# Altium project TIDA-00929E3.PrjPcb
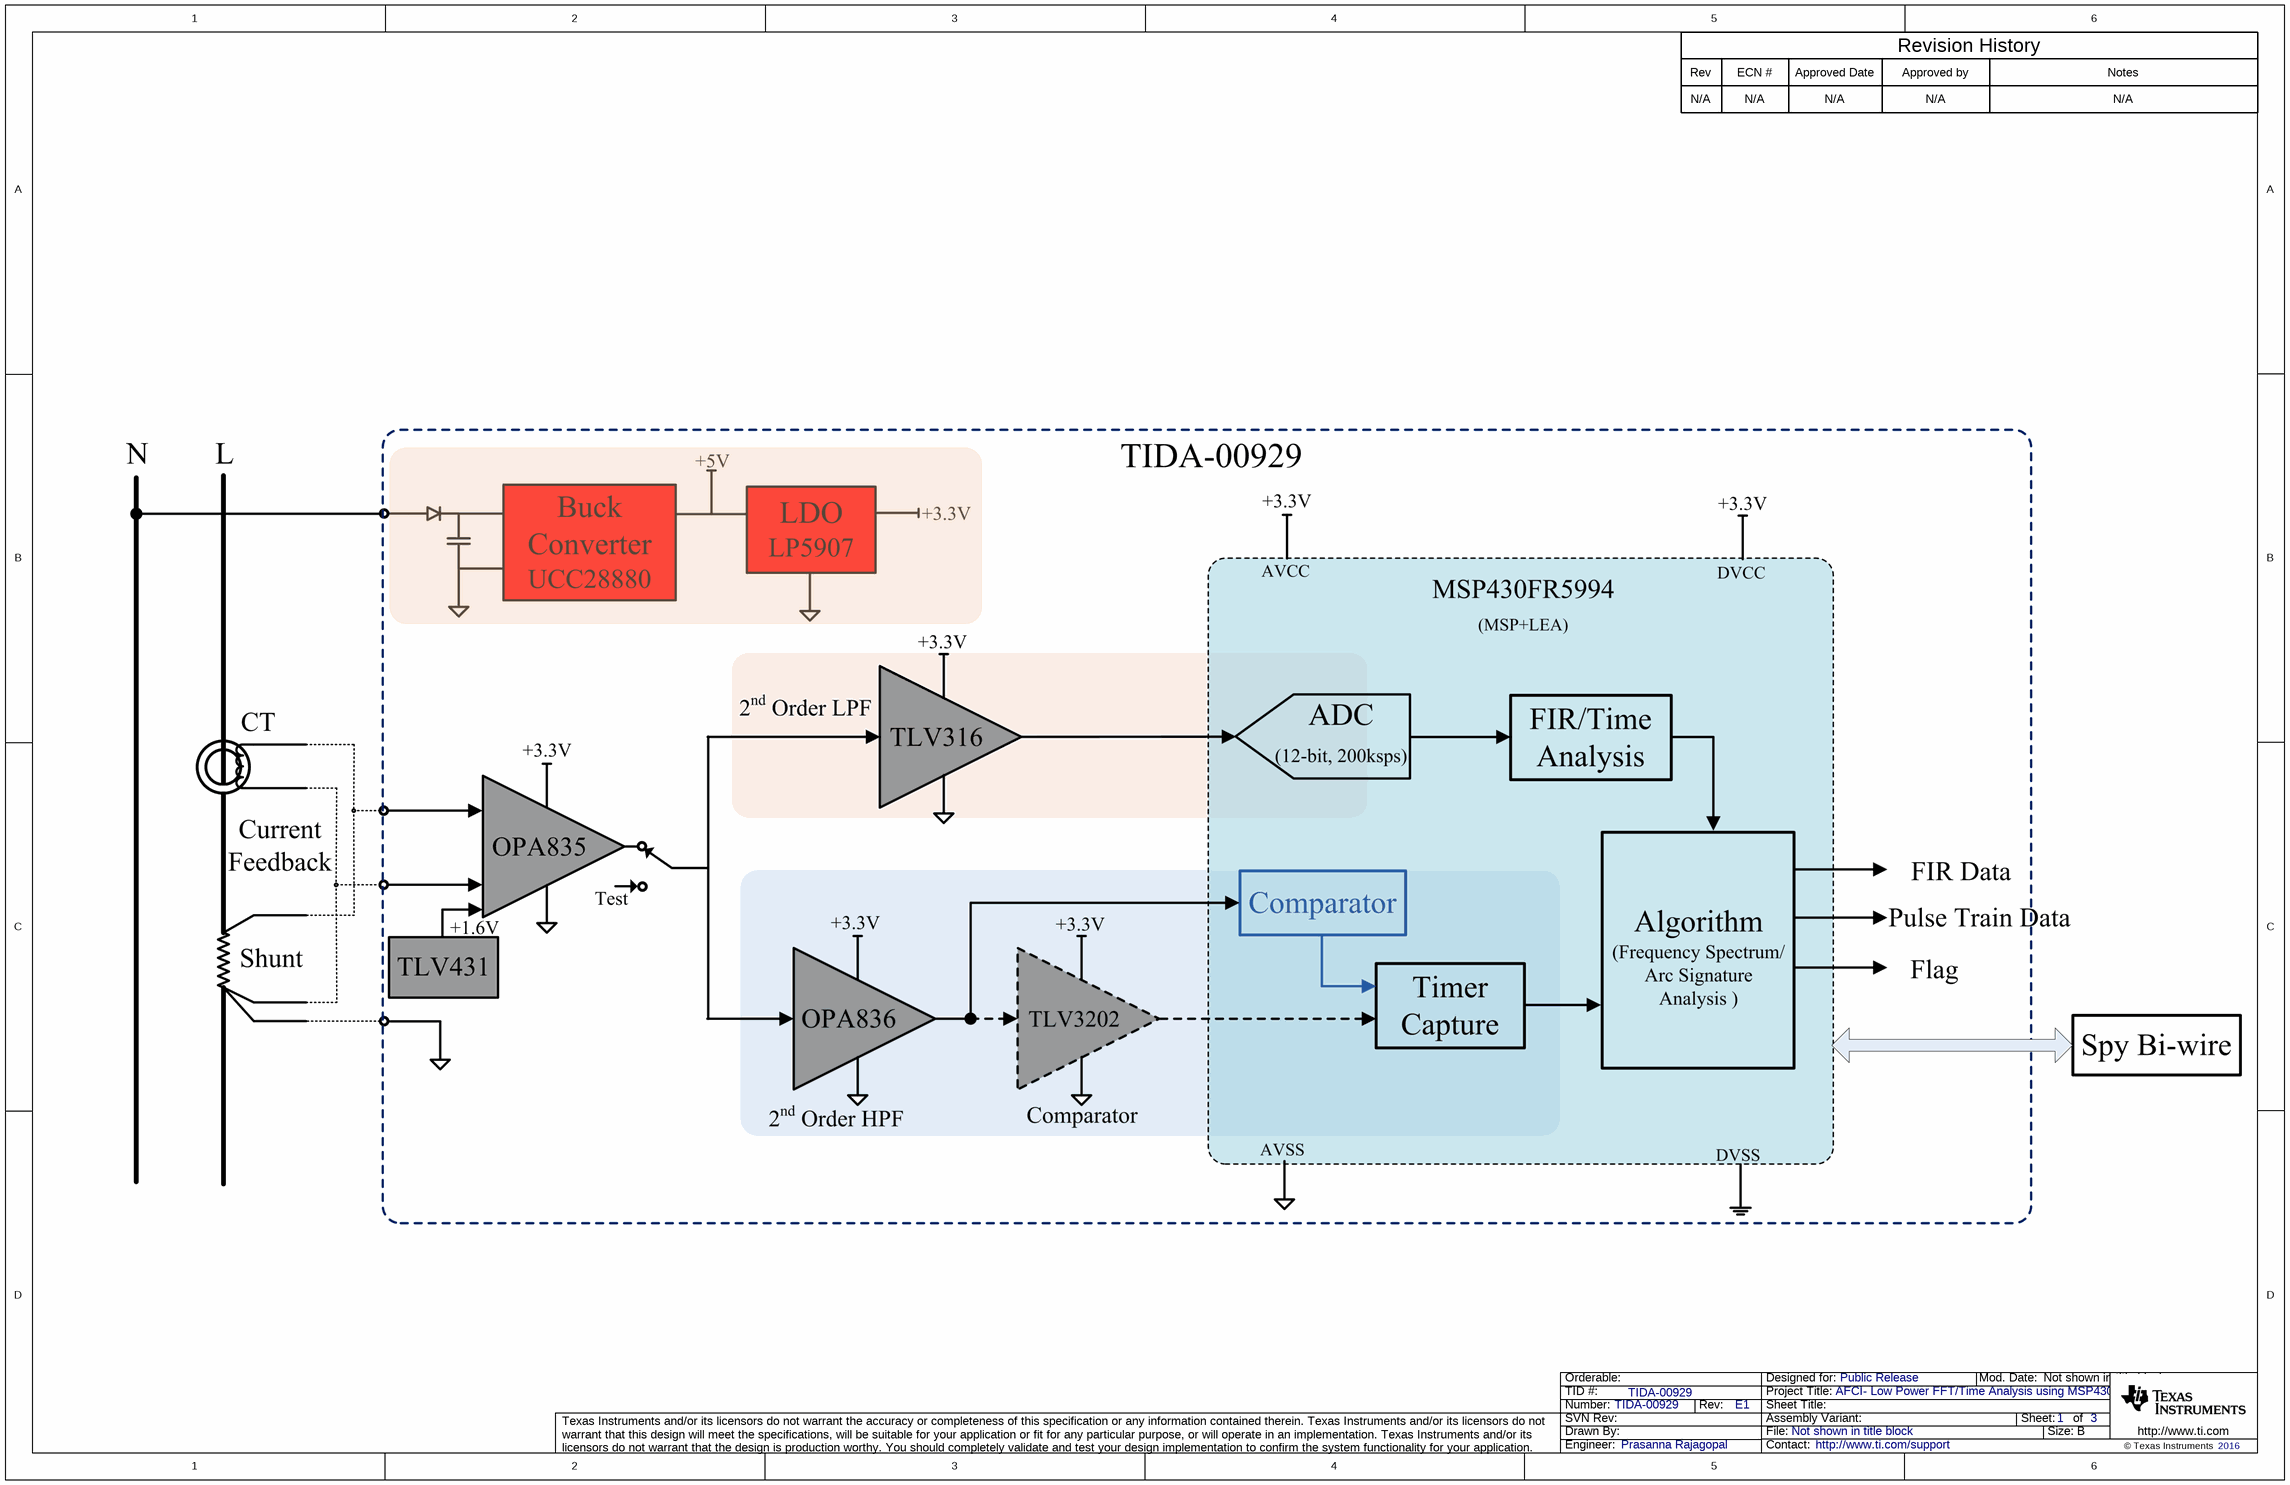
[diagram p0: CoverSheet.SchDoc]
CopyrightYear: 2016; PCB_Layout: Prasanna Rajagopal; PCB_Rev: E1; PRJ_Customer: Public Release; PRJ_Engineer: Prasanna Rajagopal; PRJ_Number: TIDA-00929; PRJ_Title: AFCI- Low Power FFT/Time Analysis using MSP430+LEA; SCH_Rev: E1; TechSupport: http://www.ti.com/support; TID: TIDA-00929
5 sheets, 155 parts. Net scope: global (net labels, ports and power ports of the same name join across sheets).
Board file: PCB1.PcbDoc
Sheets:
  CoverSheet.SchDoc
  BlankSheet.SchDoc
  EVM_Hardware.SchDoc
  Sheet1.SchDoc
  Sheet2.SchDoc

## Sheet CoverSheet.SchDoc
size 431 x 279 mm; Date: Not shown in title block; ApprovedBy: Not shown in title block; CheckedBy: Not shown in title block; Author: Not shown in title block; CompanyName: Not shown in title block; Engineer: Not shown in title block; Organization: Not shown in title block; Address1: Not shown in title block; Address2: Not shown in title block; Address3: Not shown in title block; Address4: Not shown in title block; DocumentNumber: 1; Revision: Use project parameter SCH_Rev; SheetNumber: 1; SheetTotal: 3; PageSetup: Record=PageOptions¦CenterHorizontal=True¦CenterVertical=True¦PrintScale=1.00¦XCorrection=1.00¦YCorrection=1.00¦PrintKind=0¦BorderSize=5000000¦LeftOffset=0¦BottomOffset=0¦Orientation=2¦PaperLength=1000¦PaperWidth=1000¦Scale=100¦PaperSource=15¦PrintQuality=600¦MediaType=1¦DitherType=10¦PaperKind=Letter¦PrintScaleMode=1

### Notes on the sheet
- Rev
- N/A
- ECN #
- Approved Date
- Approved by
- Revision History
- Notes

## Sheet BlankSheet.SchDoc
size 431 x 279 mm; Date: Not shown in title block; ApprovedBy: Not shown in title block; CheckedBy: Not shown in title block; Author: Not shown in title block; CompanyName: Not shown in title block; Engineer: Not shown in title block; Organization: Not shown in title block; Address1: Not shown in title block; Address2: Not shown in title block; Address3: Not shown in title block; Address4: Not shown in title block; DocumentNumber: 1; Revision: Use project parameter SCH_Rev; SheetNumber: 2; SheetTotal: 3; PageSetup: Record=PageOptions¦CenterHorizontal=True¦CenterVertical=True¦PrintScale=1.00¦XCorrection=1.00¦YCorrection=1.00¦PrintKind=0¦BorderSize=5000000¦LeftOffset=0¦BottomOffset=0¦Orientation=2¦PaperLength=1000¦PaperWidth=1000¦Scale=100¦PaperSource=15¦PrintQuality=600¦MediaType=1¦DitherType=10¦PaperKind=Letter¦PrintScaleMode=1

## Sheet EVM_Hardware.SchDoc
size 431 x 279 mm; Date: Not shown in title block; ApprovedBy: Not shown in title block; CheckedBy: Not shown in title block; Author: Not shown in title block; CompanyName: Not shown in title block; DrawnBy: Prasanna Rajagopal; Engineer: Not shown in title block; Organization: Not shown in title block; Address1: Not shown in title block; Address2: Not shown in title block; Address3: Not shown in title block; Address4: Not shown in title block; DocumentNumber: 1; Revision: Use project parameter SCH_Rev; SheetNumber: 3; SheetTotal: 3; PageSetup: Record=PageOptions¦CenterHorizontal=True¦CenterVertical=True¦PrintScale=1.00¦XCorrection=1.00¦YCorrection=1.00¦PrintKind=0¦BorderSize=5000000¦LeftOffset=0¦BottomOffset=0¦Orientation=2¦PaperLength=1000¦PaperWidth=1000¦Scale=100¦PaperSource=15¦PrintQuality=600¦MediaType=1¦DitherType=10¦PaperKind=Letter¦PrintScaleMode=1
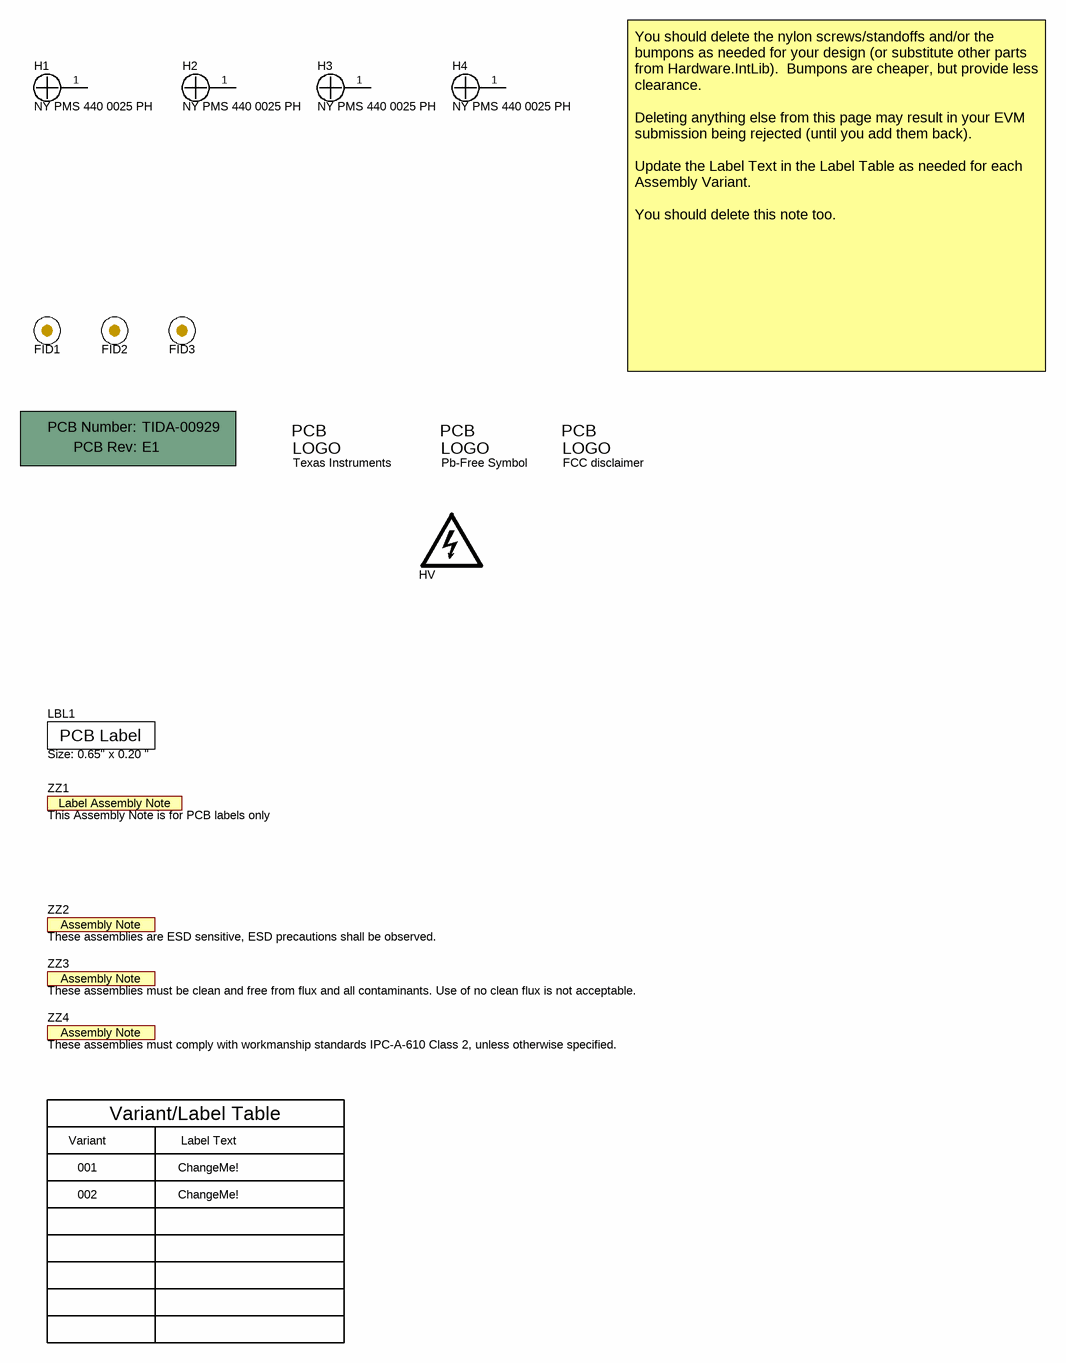
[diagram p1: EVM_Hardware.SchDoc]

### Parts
!PCB  Printed Circuit Board  (value not drawn)  (mechanical)
FID1  Fiducial  [Fiducial10-20]  (value not drawn)
FID2  Fiducial  [Fiducial10-20]  (value not drawn)
FID3  Fiducial  [Fiducial10-20]  (value not drawn)
H1  NY PMS 440 0025 PH  [NY PMS 440 0025 PH]
H2  NY PMS 440 0025 PH  [NY PMS 440 0025 PH]
H3  NY PMS 440 0025 PH  [NY PMS 440 0025 PH]
H4  NY PMS 440 0025 PH  [NY PMS 440 0025 PH]
HV  DANGER HIGH VOLTAGE  [IEC_HighVoltage_Small]  (value not drawn)  (no BOM)
LBL1  Size: 0.65" x 0.20 "  [Label_650x200]
Logo1  Texas Instruments  [TI_Stacked_Overlay_Small]  (no BOM)
Logo2  Pb-Free Symbol  [Pb-Free_Overlay_Small]  (no BOM)
Logo3  FCC disclaimer  [FCC_disclaimer]  (no BOM)
ZZ1  This Assembly Note is for PCB labels only  [AssemblyNoteLabel]  (no BOM)
ZZ2  These assemblies are ESD sensitive, ESD precautions shall be observed.  [AssemblyNote]  (no BOM)
ZZ3  These assemblies must be clean and free from flux and all contaminants. Use of no clean flux is not acceptable.  [AssemblyNote]  (no BOM)
ZZ4  These assemblies must comply with workmanship standards IPC-A-610 Class 2, unless otherwise specified.  [AssemblyNote]  (no BOM)

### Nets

Not connected (* = marked no-connect by the designer): H1 1; H2 1; H3 1; H4 1

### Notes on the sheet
- You should delete the nylon screws/standoffs and/or the bumpons as needed for your design (or substitute other parts from Hardware.IntLib).  Bumpons are cheaper, but provide less clearance.
  Deleting anything else from this page may result in your EVM submission being rejected (until you add them back).
  Update the Label Text in the Label Table as needed for each Assembly Variant.
  You should delete this note too.
- Variant
- Variant/Label Table
- Label Text
- 001
- 002
- ChangeMe!

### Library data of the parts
!PCB = PCB: Manufacturer: Any; PartNumber: TIDA-00929; SymbolCreator: a0412235
FID1-FID3 = Fiducial: Fiducial mark.  There is nothing to buy or mount.; SymbolCreator: codlsc
H1-H4 = NY PMS 440 0025 PH: Machine Screw, Round, #4-40 x 1/4, Nylon, Philips panhead; Manufacturer: B&F Fastener Supply; CompType: Hardware; SymbolCreator: codlsc; U/M: EA
HV = IEC_HighVoltage: IEC 61010-1 High Voltage Warning; SymbolCreator: a0412235
LBL1 = THT-14-423-10: Thermal Transfer Printable Labels, 0.650" W x 0.200" H - 10,000 per roll; Manufacturer: Brady; SymbolCreator: a0412235; CompType: Label
Logo1 = TI_Logo: Texas Instrument Corporate Signature; SymbolCreator: codlsc
Logo2 = Pb-Free: SymbolCreator: a0412235
Logo3 = FCC_disclaimer: SymbolCreator: codlsc
ZZ1 = AssemblyNoteLabel: SymbolCreator: a0412235
ZZ2-ZZ4 = AssemblyNote: SymbolCreator: codlsc

## Sheet Sheet1.SchDoc
size 431 x 279 mm; Date: Not shown in title block; ApprovedBy: Not shown in title block; CheckedBy: Not shown in title block; Author: Not shown in title block; CompanyName: Not shown in title block; Engineer: Not shown in title block; Organization: Not shown in title block; Address1: Not shown in title block; Address2: Not shown in title block; Address3: Not shown in title block; Address4: Not shown in title block; DocumentNumber: 1; Revision: Use project parameter SCH_Rev; SheetNumber: 2; SheetTotal: 3; PageSetup: Record=PageOptions¦CenterHorizontal=True¦CenterVertical=True¦PrintScale=1.00¦XCorrection=1.00¦YCorrection=1.00¦PrintKind=0¦BorderSize=5000000¦LeftOffset=0¦BottomOffset=0¦Orientation=2¦PaperLength=1000¦PaperWidth=1000¦Scale=100¦PaperSource=15¦PrintQuality=600¦MediaType=1¦DitherType=10¦PaperKind=Letter¦PrintScaleMode=1
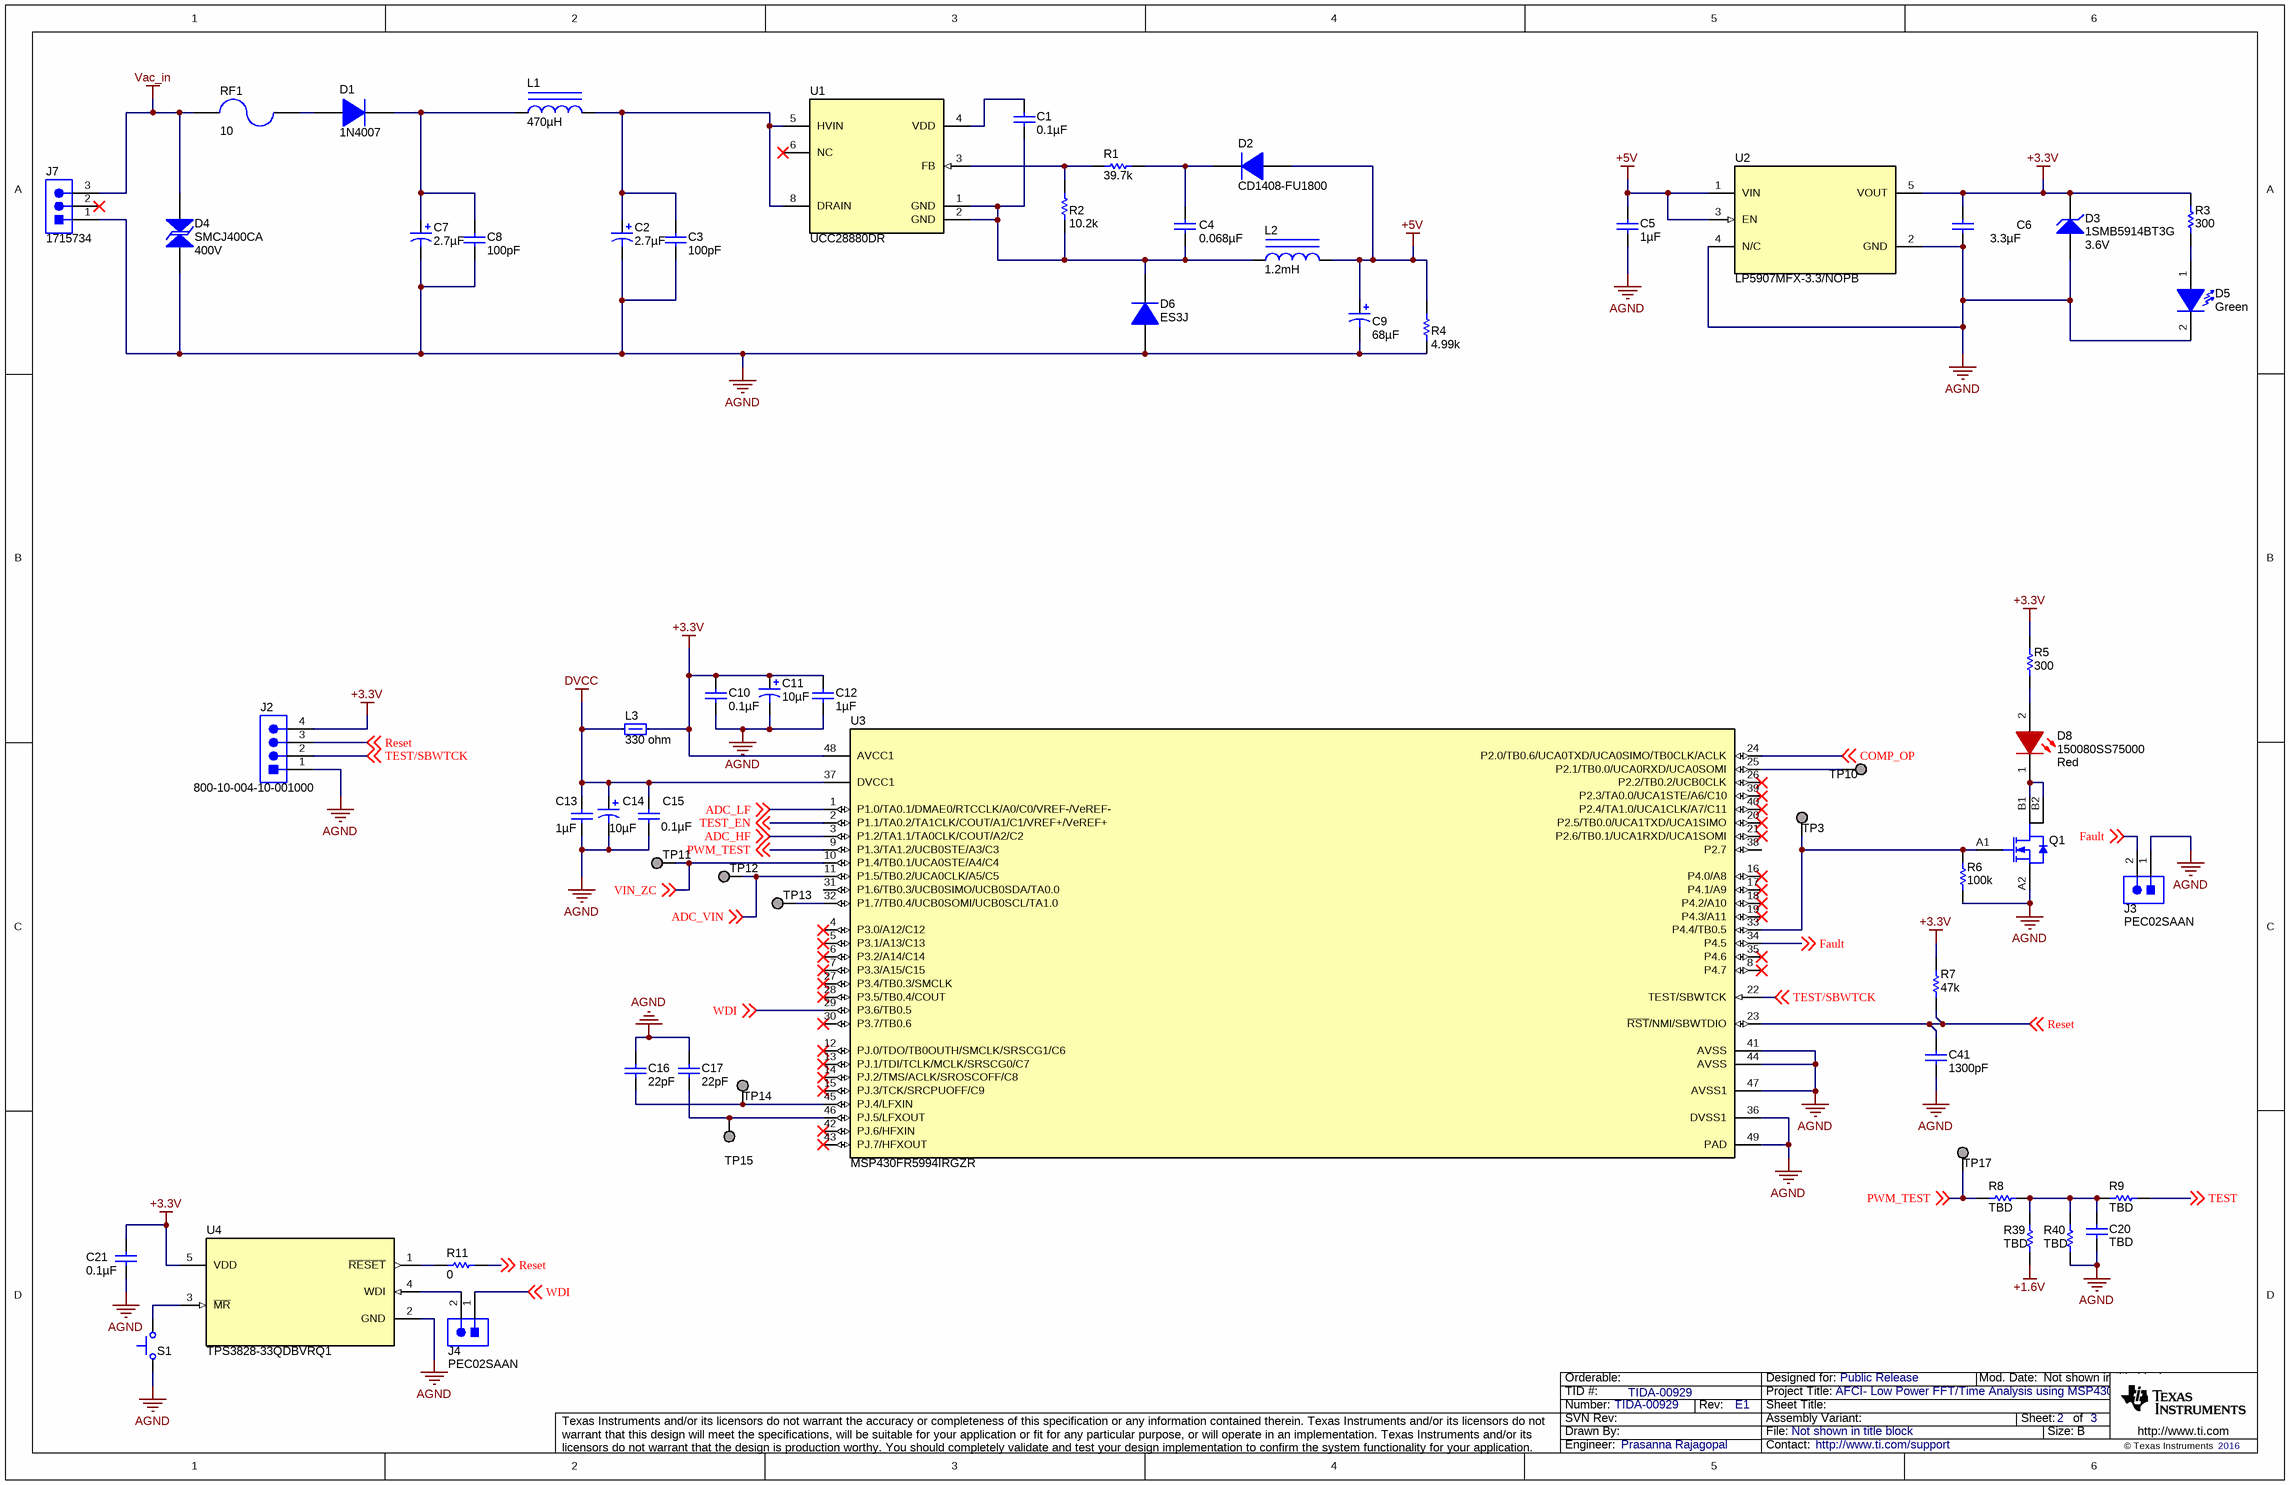
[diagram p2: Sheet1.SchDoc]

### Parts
C1  ValueDisplayed: 0.1µF  [0402]  (hidden comment: C1005X5R1A104K050BA)
C2  ValueDisplayed: 2.7µF  [ULR_800X1000]  (hidden comment: ULR2H2R7MNL1GS)
C3  ValueDisplayed: 100pF  [0805_HV]  (hidden comment: CC0805JRNP09BN101)
C4  ValueDisplayed: 0.068µF  [0402]  (hidden comment: GRM155R61A683KA01D)
C5  ValueDisplayed: 1µF  [0402]  (hidden comment: GRM155R61A105KE15D)
C6  ValueDisplayed: 3.3µF  [0603]  (hidden comment: GRM188R61A335KE15D)
C7  ValueDisplayed: 2.7µF  [ULR_800X1000]  (hidden comment: ULR2H2R7MNL1GS)
C8  ValueDisplayed: 100pF  [0805_HV]  (hidden comment: CC0805JRNP09BN101)
C9  ValueDisplayed: 68µF  [SM_RADIAL_6.3AMM]  (hidden comment: UUD1A680MCL1GS)
C10  ValueDisplayed: 0.1µF  [0402]  (hidden comment: C1005X5R1A104K050BA)
C11  ValueDisplayed: 10µF  [3216-18]  (hidden comment: TAJA106M010RNJ)
C12  ValueDisplayed: 1µF  [0805_HV]  (hidden comment: LMK212B7105KD-T)
C13  ValueDisplayed: 1µF  [0805_HV]  (hidden comment: LMK212B7105KD-T)
C14  ValueDisplayed: 10µF  [3216-18]  (hidden comment: TAJA106M010RNJ)
C15  ValueDisplayed: 0.1µF  [0402]  (hidden comment: C1005X5R1A104K050BA)
C16  ValueDisplayed: 22pF  [0805_HV]  (hidden comment: GQM2195C1H220JB01D)
C17  ValueDisplayed: 22pF  [0805_HV]  (hidden comment: GQM2195C1H220JB01D)
C20  ValueDisplayed: TBD  [0805_HV]  (hidden comment: GQM2195C1H220JB01D)
C21  ValueDisplayed: 0.1µF  [0603]  (hidden comment: 06033C104JAT2A)
C41  ValueDisplayed: 1300pF  [0603]  (hidden comment: 06035C132JAT2A)
D1  1N4007  [DO-41]
D2  CD1408-FU1800  [Diode_1408]
D3  1SMB5914BT3G  value 3.6V  [SMB]
D4  SMCJ400CA  value 400V  [DO-214AB-Bi]
D5  value Green  [LG L29K_GREEN]  (hidden comment: LG L29K-G2J1-24-Z)
D6  ES3J  [SMC]
D8  150080SS75000  value Red  [WL-SMCW_RED_0805]
J2  800-10-004-10-001000  [Mill-Max_800-10-004-10-001000]
J3  PEC02SAAN  [CONN_PEC02SAAN]
J4  PEC02SAAN  [CONN_PEC02SAAN]
J7  1715734  [Phoenix_1715734]
L1  ValueDisplayed: 470µH  [SDR0302]  (hidden comment: SDR0302-471KL)
L2  ValueDisplayed: 1.2mH  [MSS1210]  (hidden comment: MSS1210-125KE)
L3  value 330 ohm  [0603]  (hidden comment: BLM18SG331TN1D)
Q1  CSD13201W10  [uSMD_4A]  (value not drawn)
R1  ValueDisplayed: 39.7k  [0805_HV]  (hidden comment: RT0805BRD0739K7L)
R2  ValueDisplayed: 10.2k  [0402]  (hidden comment: CRCW040210K2FKED)
R3  ValueDisplayed: 300  [0603]  (hidden comment: CRCW0603300RJNEA)
R4  ValueDisplayed: 4.99k  [0402]  (hidden comment: CRCW04024K99FKED)
R5  ValueDisplayed: 300  [0603]  (hidden comment: CRCW0603300RJNEA)
R6  ValueDisplayed: 100k  [0603]  (hidden comment: CRCW0603100KFKEA)
R7  ValueDisplayed: 47k  [0603]  (hidden comment: CRCW060347K0JNEA)
R8  ValueDisplayed: TBD  [0603]  (hidden comment: CRCW06030000Z0EA)
R9  ValueDisplayed: TBD  [0603]  (hidden comment: CRCW06030000Z0EA)
R11  ValueDisplayed: 0  [0603]  (hidden comment: CRCW06030000Z0EA)
R39  ValueDisplayed: TBD  [0603]  (hidden comment: CRCW06030000Z0EA)
R40  ValueDisplayed: TBD  [0603]  (hidden comment: CRCW06030000Z0EA)
RF1  ValueDisplayed: 10  [AC03]  (hidden comment: AC03000001009JACCS)
S1  EVQ-21505R  [SW_EVQ-21x05]  (value not drawn)
TP3  TESTPOINT  [TP_SM_1MM]  (value not drawn)  (no BOM)
TP10  TESTPOINT  [TP_SM_1MM]  (value not drawn)  (no BOM)
TP11  TESTPOINT  [TP_SM_1MM]  (value not drawn)  (no BOM)
TP12  TESTPOINT  [TP_SM_1MM]  (value not drawn)  (no BOM)
TP13  TESTPOINT  [TP_SM_1MM]  (value not drawn)  (no BOM)
TP14  TESTPOINT  [TP_SM_1MM]  (value not drawn)  (no BOM)
TP15  TESTPOINT  [TP_SM_1MM]  (value not drawn)  (no BOM)
TP17  TESTPOINT  [TP_SM_1MM]  (value not drawn)  (no BOM)
U1  UCC28880DR  [D0007A_N]
U2  LP5907MFX-3.3/NOPB  [DBV0005A_N]
U3  MSP430FR5994IRGZR  [RGZ0048A]
U4  TPS3828-33QDBVRQ1  [DBV0005A_N]

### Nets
+1.6V: R39.1
+3.3V: C6.1 C10.1 C11.1(+) C12.1 C21.1 D3.1(K) J2.4 L3.2 R3.2 R5.1 R7.2 U2.5(VOUT) U3.48(AVCC1) U4.5(VDD)
+5V: C5.1 C9.1(+) D2.2(A) L2.2 R4.2 U2.1(VIN) U2.3(EN)
AGND: C2.2(-) C3.2 C5.2 C6.2 C7.2(-) C8.2 C9.2(-) C10.2 C11.2(-) C12.2 C13.2 C14.2(-) C15.2 C16.1 C17.1 C20.2 C21.2 C41.2 D3.2(A) D4.1 D5.2(K) D6.2(A) J2.1 J3.1 J7.1 Q1.A2(S) R4.1 R6.1 R40.1 S1.1 U2.2(GND) U2.4(N/C) U3.36(DVSS1) U3.41(AVSS) U3.44(AVSS) U3.47(AVSS1) U3.49(PAD) U4.2(GND)
DVCC: C13.1 C14.1(+) C15.1 L3.1 U3.37(DVCC1)
Vac_in: D4.2 J7.3 RF1.2
ADC_HF: U3.3(P1.2/TA1.1/TA0CLK/COUT/A2/C2) ; off-sheet ADC_HF
ADC_LF: U3.1(P1.0/TA0.1/DMAE0/RTCCLK/A0/C0/VREF-/VeREF-) ; off-sheet ADC_LF
ADC_VIN: TP12.1 U3.11(P1.5/TB0.2/UCA0CLK/A5/C5) ; off-sheet ADC_VIN
COMP_OP: U3.24(P2.0/TB0.6/UCA0TXD/UCA0SIMO/TB0CLK/ACLK) ; off-sheet COMP_OP
Fault: J3.2 U3.34(P4.5) ; off-sheet Fault
PWM_TEST: R8.1 TP17.1 U3.9(P1.3/TA1.2/UCB0STE/A3/C3) ; off-sheet PWM_TEST
Reset: C41.1 J2.3 R7.1 R11.2 U3.23(~{RST}/NMI/SBWTDIO) ; off-sheet Reset
TEST: R9.2 ; off-sheet TEST
TEST/SBWTCK: J2.2 U3.22(TEST/SBWTCK) ; off-sheet TEST/SBWTCK
TEST_EN: U3.2(P1.1/TA0.2/TA1CLK/COUT/A1/C1/VREF+/VeREF+) ; off-sheet TEST_EN
VIN_ZC: TP11.1 U3.10(P1.4/TB0.1/UCA0STE/A4/C4) ; off-sheet VIN_ZC
WDI: J4.1 U3.29(P3.6/TB0.5) ; off-sheet WDI
NetC1_1: C1.1 U1.4(VDD)
NetC1_2: C1.2 C4.2 D6.1(K) L2.1 R2.1 U1.1(GND) U1.2(GND)
NetC2_1: C2.1(+) C3.1 L1.2 U1.5(HVIN) U1.8(DRAIN)
NetC4_1: C4.1 D2.1(K) R1.2
NetC7_1: C7.1(+) C8.1 D1.1(K) L1.1
NetC16_2: C16.2 TP14.1 U3.45(PJ.4/LFXIN)
NetC17_2: C17.2 TP15.1 U3.46(PJ.5/LFXOUT)
NetC20_1: C20.1 R8.2 R9.1 R39.2 R40.2
NetD1_2: D1.2(A) RF1.1
NetD5_1: D5.1(A) R3.1
NetD8_1: D8.1(K) Q1.B1(D) Q1.B2(D)
NetD8_2: D8.2(A) R5.2
NetJ4_2: J4.2 U4.4(WDI)
NetQ1_A1: Q1.A1(G) R6.2 TP3.1 U3.33(P4.4/TB0.5)
NetR1_1: R1.1 R2.2 U1.3(FB)
NetR11_1: R11.1 U4.1(~{RESET})
NetS1_2: S1.2 U4.3(~{MR})
NetTP10_1: TP10.1 U3.25(P2.1/TB0.0/UCA0RXD/UCA0SOMI)
NetTP13_1: TP13.1 U3.32(P1.7/TB0.4/UCB0SOMI/UCB0SCL/TA1.0)

Not connected (* = marked no-connect by the designer): J7 2*; U1 6(NC)*; U3 4(P3.0/A12/C12)* 5(P3.1/A13/C13)* 6(P3.2/A14/C14)* 7(P3.3/A15/C15)* 8(P4.7)* 12(PJ.0/TDO/TB0OUTH/SMCLK/SRSCG1/C6)* 13(PJ.1/TDI/TCLK/MCLK/SRSCG0/C7)* 14(PJ.2/TMS/ACLK/SROSCOFF/C8)* 15(PJ.3/TCK/SRCPUOFF/C9)* 16(P4.0/A8)* 17(P4.1/A9)* 18(P4.2/A10)* 19(P4.3/A11)* 20(P2.5/TB0.0/UCA1TXD/UCA1SIMO)* 21(P2.6/TB0.1/UCA1RXD/UCA1SOMI)* 26(P2.2/TB0.2/UCB0CLK)* 27(P3.4/TB0.3/SMCLK)* 28(P3.5/TB0.4/COUT)* 30(P3.7/TB0.6)* 31(P1.6/TB0.3/UCB0SIMO/UCB0SDA/TA0.0) 35(P4.6)* 38(P2.7) 39(P2.3/TA0.0/UCA1STE/A6/C10)* 40(P2.4/TA1.0/UCA1CLK/A7/C11)* 42(PJ.6/HFXIN)* 43(PJ.7/HFXOUT)*

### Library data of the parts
C1 C10 C15 = C1005X5R1A104K050BA: CAP, CERM, 0.1 µF, 10 V, +/- 10%, X5R, 0402; Manufacturer: TDK; Polarized: N; CompType: Capacitor; Value: 0.1uF; U/M: EA; Cap_F: 0.0000001; Tolerance_%: 10; Value1: Unknown; Value2: 10V; TaMin_C: -55; TaMax_C: 85; SizeArea_mm2: 0.5; SizeAreaWB_mm2: 3; SizeX_mm: 1; SizeZ_mm: 0.6; AEC Category: Q200
C2 C7 = ULR2H2R7MNL1GS: CAP, AL, 2.7 µF, 500 V, +/- 20%, SMD; Manufacturer: Nichicon; Polarized: Y; CompType: Capacitor; Value: 2.7uF; U/M: EA; Cap_F: 0.0000027; Tolerance_%: 20; Value1: Unknown; VDC_V: 500; Value2: 500V; IRMS_A: 0.02; TaMin_C: -40; TaMax_C: 105; Cap_Case: 8X10mm; SizeAreaWB_mm2: 106.09; SizeArea_mm2: 68.89; SizeX_mm: 8.3; SizeZ_mm: 11; AEC Category: Q200; AEC Qualified: N
C3 C8 = CC0805JRNP09BN101: CAP, CERM, 100 pF, 50 V, +/- 5%, C0G/NP0, 0805; Manufacturer: Yageo America; Polarized: N; CompType: Capacitor; Value: 100pF; U/M: EA; Cap_F: 0.0000000001; Tolerance_%: 5; Value1: Unknown; VDC_V: 50; Value2: 50V; TaMin_C: -55; TaMax_C: 125; Cap_Case: 0805; SizeArea_mm2: 2.5; SizeAreaWB_mm2: 6.75; SizeX_mm: 2; SizeY_mm: 1.25; SizeZ_mm: 1.45; AEC Category: Q200
C4 = GRM155R61A683KA01D: CAP, CERM, 0.068 µF, 10 V, +/- 10%, X5R, 0402; Manufacturer: MuRata; Polarized: N; CompType: Capacitor; Value: 0.068uF; U/M: EA; Cap_F: 0.000000068; Tolerance_%: 10; Value1: Unknown; Value2: 10V; TaMin_C: -55; TaMax_C: 85; SizeArea_mm2: 0.5; SizeAreaWB_mm2: 3; SizeX_mm: 1; SizeZ_mm: 0.6; AEC Category: Q200
C5 = GRM155R61A105KE15D: CAP, CERM, 1 µF, 10 V, +/- 10%, X5R, 0402; Manufacturer: MuRata; Polarized: N; CompType: Capacitor; Value: 1uF; U/M: EA; Cap_F: 0.000001; Tolerance_%: 10; Value1: Unknown; Value2: 10V; TaMin_C: -55; TaMax_C: 85; SizeArea_mm2: 0.5; SizeAreaWB_mm2: 3; SizeX_mm: 1; SizeZ_mm: 0.6; AEC Category: Q200
C6 = GRM188R61A335KE15D: CAP, CERM, 3.3 µF, 10 V, +/- 10%, X5R, 0603; Manufacturer: MuRata; Polarized: N; CompType: Capacitor; Value: 3.3uF; U/M: EA; Cap_F: 0.0000033; Tolerance_%: 10; ESR_ohm: 0.005; Value1: 0.005 ohm; Value2: 10V; IRMS_A: 1.7; TaMin_C: -55; TaMax_C: 85; SizeArea_mm2: 1.28; SizeAreaWB_mm2: 4.68; SizeX_mm: 1.6; SizeY_mm: 0.8; SizeZ_mm: 1; AEC Category: Q200
C9 = UUD1A680MCL1GS: CAP, AL, 68 µF, 10 V, +/- 20%, 0.44 ohm, SMD; Manufacturer: Nichicon; Polarized: Y; CompType: Capacitor; Value: 68uF; U/M: EA; Cap_F: 0.000068; Tolerance_%: 20; VDC_V: 10; Value2: 10V; ESR_ohm: 0.44; IRMS_A: 0.23; TaMin_C: -55; TaMax_C: 105; Cap_Case: 6.3x5.8; AEC Category: Q200
C11 C14 = TAJA106M010RNJ: CAP, TA, 10 µF, 10 V, +/- 20%, 3 ohm, SMD; Manufacturer: AVX; Polarized: Y; CompType: Capacitor; Value: 10uF; U/M: EA; Cap_F: 0.00001; Tolerance_%: 20; Value1: 3 ohm; VDC_V: 10; Value2: 10V; ESR_ohm: 3; TaMin_C: -55; TaMax_C: 125; SizeAreaWB_mm2: 10.92; SizeArea_mm2: 5.12; SizeX_mm: 3.2; SizeY_mm: 1.6; SizeZ_mm: 1.8; AEC Category: Q200
C12 C13 = LMK212B7105KD-T: CAP, CERM, 1 µF, 10 V, +/- 10%, X7R, 0805; Manufacturer: Taiyo Yuden; Polarized: N; CompType: Capacitor; Value: 1uF; U/M: EA; Cap_F: 0.000001; Tolerance_%: 10; Value1: Unknown; Value2: 10V; TaMin_C: -55; TaMax_C: 125; Cap_Case: 0805; SizeArea_mm2: 2.5; SizeAreaWB_mm2: 6.75; SizeX_mm: 2; SizeY_mm: 1.25; SizeZ_mm: 1.45; AEC Category: Q200
C16 C17 C20 = GQM2195C1H220JB01D: CAP, CERM, 22 pF, 50 V, +/- 5%, C0G/NP0, 0805; Manufacturer: MuRata; Polarized: N; CompType: Capacitor; Value: 22pF; U/M: EA; Cap_F: 0.000000000022; Tolerance_%: 5; Value1: Unknown; VDC_V: 50; Value2: 50V; TaMin_C: -55; TaMax_C: 125; Cap_Case: 0805; SizeArea_mm2: 2.5; SizeAreaWB_mm2: 6.75; SizeX_mm: 2; SizeY_mm: 1.25; SizeZ_mm: 1.45; AEC Category: Q200
C21 = 06033C104JAT2A: CAP, CERM, 0.1 µF, 25 V, +/- 5%, X7R, 0603; Manufacturer: AVX; Polarized: N; CompType: Capacitor; Value: 0.1uF; U/M: EA; Cap_F: 0.0000001; Tolerance_%: 5; ESR_ohm: 0.05; Value1: 0.05 ohm; VDC_V: 25; Value2: 25V; TaMin_C: -55; TaMax_C: 125; SizeArea_mm2: 1.28; SizeAreaWB_mm2: 4.68; SizeX_mm: 1.6; SizeY_mm: 0.8; SizeZ_mm: 1; AEC Category: Q200
C41 = 06035C132JAT2A: CAP, CERM, 1300 pF, 50 V, +/- 5%, X7R, 0603; Manufacturer: AVX; Polarized: N; CompType: Capacitor; Value: 1300pF; U/M: EA; Cap_F: 0.0000000013; Tolerance_%: 5; Value1: Unknown; VDC_V: 50; Value2: 50V; TaMin_C: -55; TaMax_C: 125; SizeArea_mm2: 1.28; SizeAreaWB_mm2: 4.68; SizeX_mm: 1.6; SizeY_mm: 0.8; SizeZ_mm: 1; AEC Category: Q200
D1 = 1N4007: Diode, P-N, 1000 V, 1 A, TH; Manufacturer: Fairchild Semiconductor; U/M: EA; Vf_V: 1.1; Value: 1000V; Value1: 1A; Value2: 1.1V; Io_A: 1; Vr_V: 1000; TJmax_C: 175; RJC_CperW: 50; SizeAreaWB_mm2: 43.424; SizeArea_mm2: 19.584; SizeX_mm: 7.2; SizeY_mm: 2.72; SizeZ_mm: 23.4; AEC Category: Q101
D2 = CD1408-FU1800: Diode, Ultrafast, 800 V, 1 A, 1408 Diode; Manufacturer: Bourns; U/M: EA; Vf_V: 2.5; Value: 800V; Value1: 1A; Value2: 2.5V; Io_A: 1; Vr_V: 800; TJmax_C: 150; RJC_CperW: 40; SizeAreaWB_mm2: 12.76; SizeArea_mm2: 6.46; SizeX_mm: 3.4; SizeY_mm: 1.9; SizeZ_mm: 1.15; AEC Category: Q101
D3 = 1SMB5914BT3G: Diode, Zener, 3.6 V, 550 mW, SMB; Manufacturer: ON Semiconductor; SymbolCreator: a0412235; U/M: EA; Power_W: 0.55; Vz_V: 3.6; Value1: 0.55W; RJA_CperW: 226; SizeAreaWB_mm2: 44.156; SizeArea_mm2: 21.336; SizeX_mm: 5.6; SizeY_mm: 3.81; SizeZ_mm: 2.6; AEC Category: Q101
D4 = SMCJ400CA: Diode, TVS, Bi, 400 V, 648 Vc, DO-214AB (no polarity); Manufacturer: Littelfuse; U/M: EA; Power_W: 6.5; Vr_V: 400; Value1: 6.5W; RJA_CperW: 75; AEC Category: Q101; AEC Qualified: N
D5 = LG L29K-G2J1-24-Z: LED, Green, SMD; Manufacturer: OSRAM; Vf_V: 1.7; Value2: 1.7V; Io_A: 0.002; Tjmax_C: 110; Value1: W; U/M: EA
D6 = ES3J: Diode, Fast Rectifier, 600 V, 3 A, SMC; Manufacturer: Fairchild Semiconductor; U/M: EA; Vf_V: 1.7; Value: 600V; Value1: 3A; Value2: 1.7V; Io_A: 3; Vr_V: 600; TJmax_C: 150; SizeAreaWB_mm2: 83.2686; SizeArea_mm2: 50.5686; SizeX_mm: 8.13; SizeY_mm: 6.22; SizeZ_mm: 2.6; AEC Category: Q101; AEC Qualified: N
D8 = 150080SS75000: LED, Red, SMD; Manufacturer: Wurth Elektronik; SymbolCreator: Altium; Type: AlInGaP; Vf_V: 1.9; Value2: 1.9V; Io_A: 0.03; Vr_V: 5; Ir_A: 2.5e-005; Tjmax_C: 85; Power_TotalModule: 0.072; Value1: 0.072W; Angle: 140; U/M: EA
J2 = 800-10-004-10-001000: Header, 100mil, 4x1, TH; Manufacturer: Mill-Max; SymbolCreator: a0412235
J3 J4 = PEC02SAAN: Header, 100mil, 2x1, Tin, TH; Manufacturer: Sullins Connector Solutions; SymbolCreator: a0412235; Pitch_mm: 2.54; Gender: Male; Shrouded: N; Row_Count: 1; Current_A: 3; Voltage_V: 1800; Cert_UL: Y
J7 = 1715734: TERM BLOCK 3POS 5.08MM, TH; Manufacturer: Phoenix Contact; SymbolCreator: a0799628; CompType: Header
L1 = SDR0302-471KL: Inductor, Drum Core, Ferrite, 470 µH, 0.11 A, 14.3 ohm, SMD; Manufacturer: Bourns; Value: 470uH; Ind_H: 470.0E-6; Imax_A: 0.11; Irms: 0.11A @ 40C rise; Isat: 0.14A @ 10% inductance drop; DCR_ohm: 14.3; Value2: 0.11A; AEC Category: Q200
L2 = MSS1210-125KE: Inductor, Shielded, Ferrite, 1.2 mH, 0.84 A, 1.21 ohm, SMD; Manufacturer: Coilcraft; Value: 1.2mH; Ind_H: 1.2E-3; Imax_A: 0.84; Irms: 0.84A @ 40C rise; Isat: 1.2A @ 30% inductance drop; DCR_ohm: 1.21; Value2: 0.84A; AEC Category: Q200
L3 = BLM18SG331TN1D: Ferrite Bead, 330 ohm @ 100 MHz, 1.5 A, 0603; Manufacturer: MuRata; Imax_A: 1.5; DCR_ohm: 0.07; Value1: 0.07 ohm; Value2: 1.5A; ZTyp@100MHz_Ohm: 330
Q1 = CSD13201W10: MOSFET, N-CH, 12 V, 1.6 A, 1x0.62x1mm; Manufacturer: Texas Instruments; Alternate Manufacturer: None; SymbolCreator: a0411947; U/M: EA; ChType: N; Value: 12V; VdsMax_V: 12; Value1: 0.026 ohm; Rdson45_ohm: 0.026; Value2: 2.3 nC; QgTyp_nC: 2.3; Vgs_V: 8; IdsMax_A: 1.6; SizeAreaWB_mm2: 3.8416; SizeArea_mm2: 0.9216; SizeX_mm: 0.96; SizeZ_mm: 0.625; AEC Category: Q101
R1 = RT0805BRD0739K7L: RES, 39.7 k, 0.1%, 0.125 W, 0805; Manufacturer: Yageo America; CompType: Resistor; Value: 39.7k; Res_ohm: 39700; Value_Code: 39k7; Tolerance_%: 0.1; Power_W: 0.125; Value2: 0.125W; VDC_V: 150; TempCo: 25 ppm/C; SizeArea_mm2: 2.5; SizeX_mm: 2; SizeY_mm: 1.25; SizeZ_mm: 1.45; EIA_Code: E192; U/M: EA; AEC Category: Q200
R2 = CRCW040210K2FKED: RES, 10.2 k, 1%, 0.063 W, 0402; Manufacturer: Vishay-Dale; CompType: Resistor; Value: 10.2k; Res_ohm: 10200; Value_Code: 10k2; Tolerance_%: 1; Power_W: 0.063; Value2: 0.063W; VDC_V: 50; TempCo: 100 ppm/C; SizeArea_mm2: 0.5; SizeZ_mm: 0.6; EIA_Code: E96; U/M: EA; AEC Category: Q200
R3 R5 = CRCW0603300RJNEA: RES, 300, 5%, 0.1 W, 0603; Manufacturer: Vishay-Dale; CompType: Resistor; Value: 300; Value_Code: 300R; Tolerance_%: 5; Power_W: 0.1; Value2: 0.1W; VDC_V: 75; TempCo: 200 ppm/C; SizeArea_mm2: 1.28; SizeX_mm: 1.6; SizeY_mm: 0.8; SizeZ_mm: 1; EIA_Code: E24; U/M: EA; AEC Category: Q200
R4 = CRCW04024K99FKED: RES, 4.99 k, 1%, 0.063 W, 0402; Manufacturer: Vishay-Dale; CompType: Resistor; Value: 4.99k; Res_ohm: 4990; Value_Code: 4k99; Tolerance_%: 1; Power_W: 0.063; Value2: 0.063W; VDC_V: 50; TempCo: 100 ppm/C; SizeArea_mm2: 0.5; SizeZ_mm: 0.6; EIA_Code: E96; U/M: EA; AEC Category: Q200
R6 = CRCW0603100KFKEA: RES, 100 k, 1%, 0.1 W, 0603; Manufacturer: Vishay-Dale; CompType: Resistor; Value: 100k; Res_ohm: 100000; Tolerance_%: 1; Power_W: 0.1; Value2: 0.1W; VDC_V: 75; TempCo: 100 ppm/C; SizeArea_mm2: 1.28; SizeX_mm: 1.6; SizeY_mm: 0.8; EIA_Code: E96; U/M: EA; AEC Category: Q200
R7 = CRCW060347K0JNEA: RES, 47 k, 5%, 0.1 W, 0603; Manufacturer: Vishay-Dale; CompType: Resistor; Value: 47k; Res_ohm: 47000; Value_Code: 47k0; Tolerance_%: 5; Power_W: 0.1; Value2: 0.1W; VDC_V: 75; TempCo: 200 ppm/C; SizeArea_mm2: 1.28; SizeX_mm: 1.6; SizeY_mm: 0.8; SizeZ_mm: 1; EIA_Code: E24; U/M: EA; AEC Category: Q200
R8 R9 R11 R39 R40 = CRCW06030000Z0EA: RES, 0, 5%, 0.1 W, 0603; Manufacturer: Vishay-Dale; CompType: Resistor; Value: 0; Value_Code: 0000; Tolerance_%: 5; Power_W: 0.1; Value2: 0.1W; VDC_V: 75; TempCo: 200 ppm/C; SizeArea_mm2: 1.28; SizeX_mm: 1.6; SizeY_mm: 0.8; SizeZ_mm: 1; EIA_Code: E24; U/M: EA; AEC Category: Q200
RF1 = AC03000001009JACCS: RES, 10, 5%, 3 W, TH, 2-Leads, Axial, Dia 5.5mm, Pin Spacing 23.8mm; Manufacturer: Vishay-Bccomponents; SymbolCreator: a0412235; CompType: Fusible Resistor; Value: 10; Value_Code: 10R0; Tolerance_%: 5; Power_W: 3; Value2: 3W; TempCo: 200 ppm/C; EIA_Code: E24; U/M: EA; AEC Category: Q200
S1 = EVQ-21505R: Switch, Tactile, SPST-NO, 0.02A, 15V, TH; Manufacturer: Panasonic; VDC_V: 15; SwitchFunction: Off-Mom; PositionCount: 1; CurrentRating_mA: 20
TP3 TP10-TP15 TP17 = TP_SM_1MM: 1mm Test Point, SMT; Manufacturer: Any
U1 = UCC28880DR: 700-V Lowest Quiescent Current Off-Line Switcher, D0007A; Manufacturer: Texas Instruments; SymbolCreator: a0411947; SizeArea_mm2: 29.4; SizeAreaWB_mm2: 55.2; SizeX_mm: 6; SizeY_mm: 4.9; SizeZ_mm: 1.75; CompType: IC; U/M: EA
U2 = LP5907MFX-3.3/NOPB: ULTRA LOW-NOISE, 250-mA LINEAR REGULATOR FOR RF AND ANALOG CIRCUITS REQUIRES NO BYPASS CAPACITOR, DBV0005A; Manufacturer: Texas Instruments; SymbolCreator: a0799628; SizeArea_mm2: 8.12; SizeAreaWB_mm2: 14.82; SizeX_mm: 2.8; SizeY_mm: 2.9; SizeZ_mm: 1.45; CompType: IC; U/M: EA
U3 = MSP430FR5994IRGZR: Mixed-Signal Microcontroller, RGZ0048A; Alternate PartNumber: MSP430FR5994IRGZT; Manufacturer: Texas Instruments; SymbolCreator: Altium; SizeArea_mm2: 49; SizeAreaWB_mm2: 81; SizeX_mm: 7; SizeZ_mm: 1; CompType: IC; U/M: EA
U4 = TPS3828-33QDBVRQ1: Voltage Monitor With Watchdog Timer, DBV0005A (SOT-5); Manufacturer: Texas Instruments; SymbolCreator: a0411947; SizeArea_mm2: 8.12; SizeAreaWB_mm2: 14.82; SizeX_mm: 2.8; SizeY_mm: 2.9; SizeZ_mm: 1.45; CompType: IC; U/M: EA

## Sheet Sheet2.SchDoc
size 431 x 279 mm; Date: Not shown in title block; ApprovedBy: Not shown in title block; CheckedBy: Not shown in title block; Author: Not shown in title block; CompanyName: Not shown in title block; Engineer: Not shown in title block; Organization: Not shown in title block; Address1: Not shown in title block; Address2: Not shown in title block; Address3: Not shown in title block; Address4: Not shown in title block; DocumentNumber: 1; Revision: Use project parameter SCH_Rev; SheetNumber: 2; SheetTotal: 3; PageSetup: Record=PageOptions¦CenterHorizontal=True¦CenterVertical=True¦PrintScale=1.00¦XCorrection=1.00¦YCorrection=1.00¦PrintKind=0¦BorderSize=5000000¦LeftOffset=0¦BottomOffset=0¦Orientation=2¦PaperLength=1000¦PaperWidth=1000¦Scale=100¦PaperSource=15¦PrintQuality=600¦MediaType=1¦DitherType=10¦PaperKind=Letter¦PrintScaleMode=1
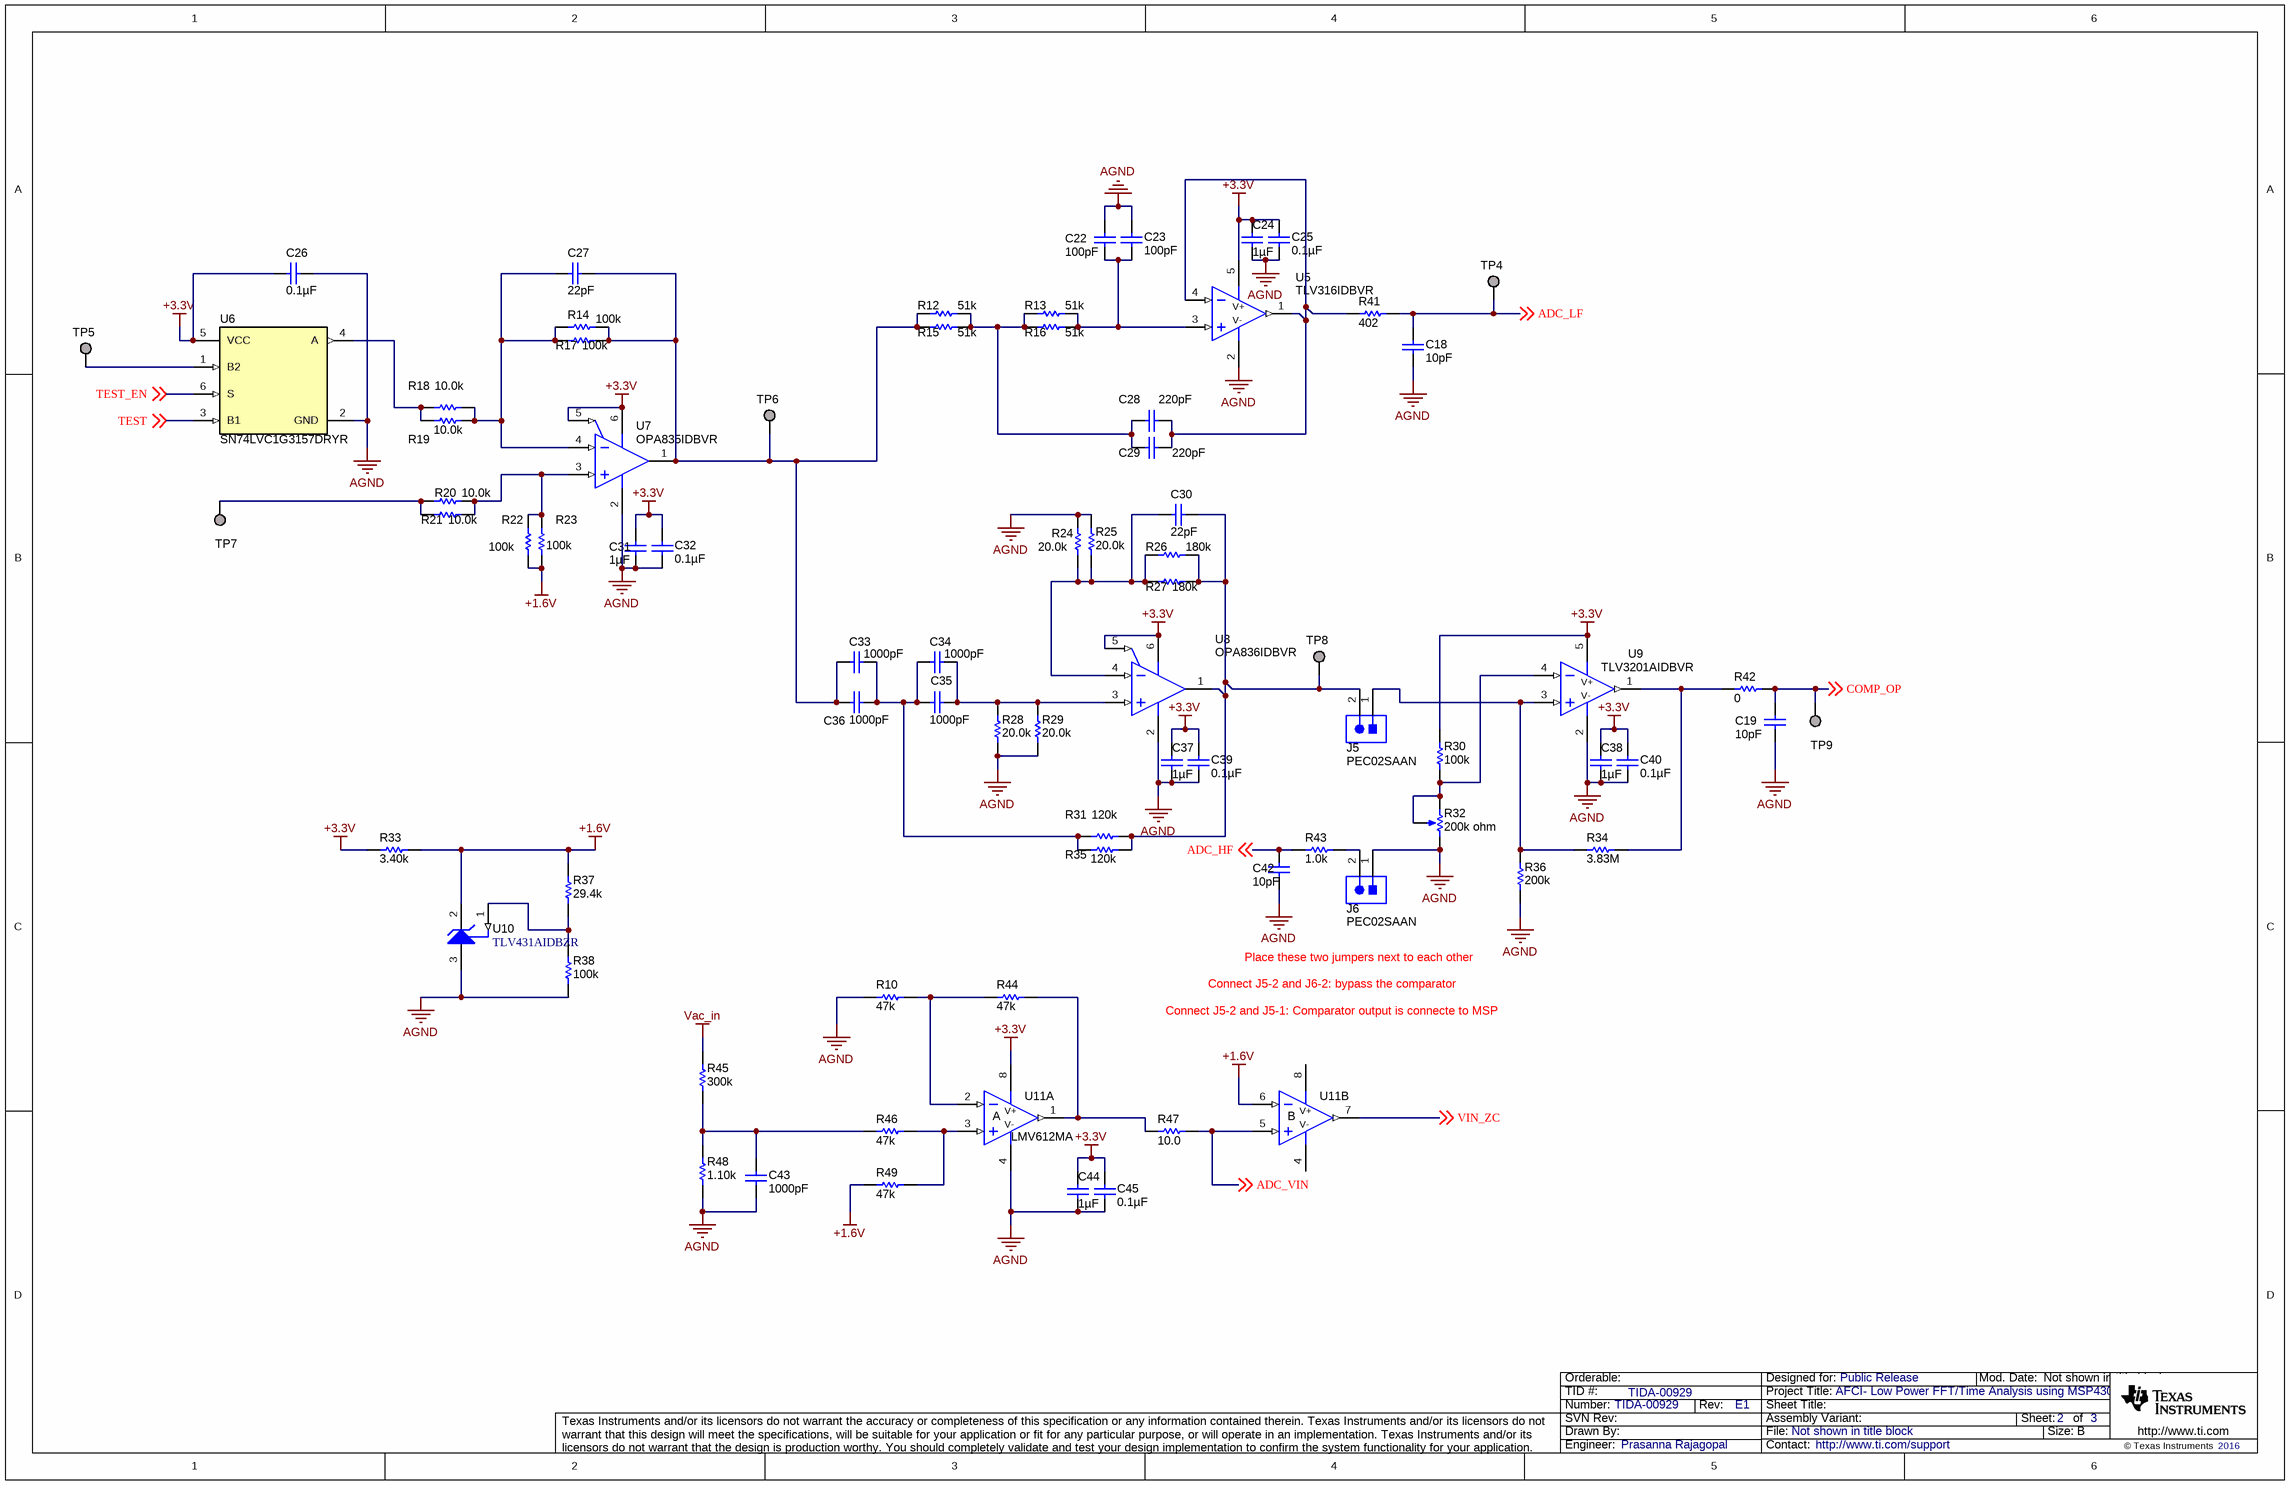
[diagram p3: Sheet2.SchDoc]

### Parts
C18  ValueDisplayed: 10pF  [0805_HV]  (hidden comment: GQM2195C2A100JB01D)
C19  ValueDisplayed: 10pF  [0805_HV]  (hidden comment: GQM2195C2A100JB01D)
C22  ValueDisplayed: 100pF  [0805_HV]  (hidden comment: CC0805JRNP09BN101)
C23  ValueDisplayed: 100pF  [0805_HV]  (hidden comment: CC0805JRNP09BN101)
C24  ValueDisplayed: 1µF  [0603]  (hidden comment: C1608X7R1C105K080AC)
C25  ValueDisplayed: 0.1µF  [0603]  (hidden comment: 06033C104JAT2A)
C26  ValueDisplayed: 0.1µF  [0603]  (hidden comment: 06033C104JAT2A)
C27  ValueDisplayed: 22pF  [0805_HV]  (hidden comment: GQM2195C1H220JB01D)
C28  ValueDisplayed: 220pF  [0805_HV]  (hidden comment: GRM2165C1H221JA01D)
C29  ValueDisplayed: 220pF  [0805_HV]  (hidden comment: GRM2165C1H221JA01D)
C30  ValueDisplayed: 22pF  [0805_HV]  (hidden comment: GQM2195C1H220JB01D)
C31  ValueDisplayed: 1µF  [0603]  (hidden comment: C1608X7R1C105K080AC)
C32  ValueDisplayed: 0.1µF  [0603]  (hidden comment: 06033C104JAT2A)
C33  ValueDisplayed: 1000pF  [0805_HV]  (hidden comment: GRM216R71E102KA01D)
C34  ValueDisplayed: 1000pF  [0805_HV]  (hidden comment: GRM216R71E102KA01D)
C35  ValueDisplayed: 1000pF  [0805_HV]  (hidden comment: GRM216R71E102KA01D)
C36  ValueDisplayed: 1000pF  [0805_HV]  (hidden comment: GRM216R71E102KA01D)
C37  ValueDisplayed: 1µF  [0603]  (hidden comment: C1608X7R1C105K080AC)
C38  ValueDisplayed: 1µF  [0603]  (hidden comment: C1608X7R1C105K080AC)
C39  ValueDisplayed: 0.1µF  [0603]  (hidden comment: 06033C104JAT2A)
C40  ValueDisplayed: 0.1µF  [0603]  (hidden comment: 06033C104JAT2A)
C42  ValueDisplayed: 10pF  [0805_HV]  (hidden comment: GQM2195C2A100JB01D)
C43  ValueDisplayed: 1000pF  [0805_HV]  (hidden comment: GRM216R71E102KA01D)
C44  ValueDisplayed: 1µF  [0603]  (hidden comment: C1608X7R1C105K080AC)
C45  ValueDisplayed: 0.1µF  [0603]  (hidden comment: 06033C104JAT2A)
J5  PEC02SAAN  [CONN_PEC02SAAN]
J6  PEC02SAAN  [CONN_PEC02SAAN]
R10  ValueDisplayed: 47k  [0603]  (hidden comment: CRCW060347K0JNEA)
R12  ValueDisplayed: 51k  [0805_HV]  (hidden comment: CRCW080551K0JNEA)
R13  ValueDisplayed: 51k  [0805_HV]  (hidden comment: CRCW080551K0JNEA)
R14  ValueDisplayed: 100k  [0805_HV]  (hidden comment: CRCW0805100KFKEA)
R15  ValueDisplayed: 51k  [0805_HV]  (hidden comment: CRCW080551K0JNEA)
R16  ValueDisplayed: 51k  [0805_HV]  (hidden comment: CRCW080551K0JNEA)
R17  ValueDisplayed: 100k  [0805_HV]  (hidden comment: CRCW0805100KFKEA)
R18  ValueDisplayed: 10.0k  [0805_HV]  (hidden comment: CRCW080510K0FKEA)
R19  ValueDisplayed: 10.0k  [0805_HV]  (hidden comment: CRCW080510K0FKEA)
R20  ValueDisplayed: 10.0k  [0805_HV]  (hidden comment: CRCW080510K0FKEA)
R21  ValueDisplayed: 10.0k  [0805_HV]  (hidden comment: CRCW080510K0FKEA)
R22  ValueDisplayed: 100k  [0805_HV]  (hidden comment: CRCW0805100KFKEA)
R23  ValueDisplayed: 100k  [0805_HV]  (hidden comment: CRCW0805100KFKEA)
R24  ValueDisplayed: 20.0k  [0805_HV]  (hidden comment: CRCW080520K0FKEA)
R25  ValueDisplayed: 20.0k  [0805_HV]  (hidden comment: CRCW080520K0FKEA)
R26  ValueDisplayed: 180k  [0805_HV]  (hidden comment: CRCW0805180KJNEA)
R27  ValueDisplayed: 180k  [0805_HV]  (hidden comment: CRCW0805180KJNEA)
R28  ValueDisplayed: 20.0k  [0805_HV]  (hidden comment: CRCW080520K0FKEA)
R29  ValueDisplayed: 20.0k  [0805_HV]  (hidden comment: CRCW080520K0FKEA)
R30  ValueDisplayed: 100k  [0805_HV]  (hidden comment: CRCW0805100KFKEA)
R31  ValueDisplayed: 120k  [0805_HV]  (hidden comment: CRCW0805120KJNEA)
R32  value 200k ohm  [Panasonic_EVM-3Y]  (hidden comment: EVM-3YSX50B25)
R33  ValueDisplayed: 3.40k  [0603]  (hidden comment: CRCW06033K40FKEA)
R34  ValueDisplayed: 3.83M  [0805_HV]  (hidden comment: CRCW08053M83FKEA)
R35  ValueDisplayed: 120k  [0805_HV]  (hidden comment: CRCW0805120KJNEA)
R36  ValueDisplayed: 200k  [0805_HV]  (hidden comment: CRCW0805200KJNEA)
R37  ValueDisplayed: 29.4k  [0603]  (hidden comment: CRCW060329K4FKEA)
R38  ValueDisplayed: 100k  [0603]  (hidden comment: CRCW0603100KFKEA)
R41  ValueDisplayed: 402  [0805_HV]  (hidden comment: CRCW0805402RFKEA)
R42  ValueDisplayed: 0  [0805_HV]  (hidden comment: CRCW08050000Z0EA)
R43  ValueDisplayed: 1.0k  [0805_HV]  (hidden comment: CRCW08051K00JNEA)
R44  ValueDisplayed: 47k  [0603]  (hidden comment: CRCW060347K0JNEA)
R45  ValueDisplayed: 300k  [2010]  (hidden comment: CRCW2010300KFKEF)
R46  ValueDisplayed: 47k  [0603]  (hidden comment: CRCW060347K0JNEA)
R47  ValueDisplayed: 10.0  [0603]  (hidden comment: CRCW060310R0FKEA)
R48  ValueDisplayed: 1.10k  [0805_HV]  (hidden comment: CRCW08051K10FKEA)
R49  ValueDisplayed: 47k  [0603]  (hidden comment: CRCW060347K0JNEA)
TP4  Suggest using a net name here  [Mill-Max_0253-0-15-15-30-27-10-0]  (value not drawn)
TP5  Suggest using a net name here  [Mill-Max_0253-0-15-15-30-27-10-0]  (value not drawn)
TP6  Suggest using a net name here  [Mill-Max_0253-0-15-15-30-27-10-0]  (value not drawn)
TP7  Suggest using a net name here  [Mill-Max_0253-0-15-15-30-27-10-0]  (value not drawn)
TP8  Suggest using a net name here  [Mill-Max_0253-0-15-15-30-27-10-0]  (value not drawn)
TP9  Suggest using a net name here  [Mill-Max_0253-0-15-15-30-27-10-0]  (value not drawn)
U5  TLV316IDBVR  [DBV0005A_N]
U6  SN74LVC1G3157DRYR  [DRY0006A]
U7  OPA835IDBVR  [DBV0006A_N]
U8  OPA836IDBVR  [DBV0006A_N]
U9  TLV3201AIDBVR  [DBV0005A_N]
U10  TLV431AIDBZR  [DBZ0003A_N]
U11  LMV612MA  [D0008A_N]  (parts A,B of 2)

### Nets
+1.6V: R22.2 R23.2 R33.2 R37.2 R49.1 U10.2(CATHODE) U11.6(IN-)
+3.3V: C24.1 C25.1 C26.2 C31.1 C32.1 C37.1 C38.1 C39.1 C40.1 C44.1 C45.1 R30.2 R33.1 U5.5(V+) U6.5(VCC) U7.5(~{PD}) U7.6(VS+) U8.5(~{PD}) U8.6(VS+) U9.5(V+) U11.8(V+)
AGND: C18.2 C19.2 C22.1 C23.1 C24.2 C25.2 C26.1 C31.2 C32.2 C37.2 C38.2 C39.2 C40.2 C42.2 C43.2 C44.2 C45.2 J6.1 R10.1 R24.2 R25.2 R28.1 R29.1 R32.3(CW) R36.1 R38.1 R48.1 U5.2(V-) U6.2(GND) U7.2(VS-) U8.2(VS-) U9.2(V-) U10.3(ANODE) U11.4(V-)
Vac_in: R45.2
ADC_HF: C42.1 R43.1 ; off-sheet ADC_HF
ADC_LF: C18.1 R41.2 TP4.1 ; off-sheet ADC_LF
ADC_VIN: R47.2 U11.5(IN+) ; off-sheet ADC_VIN
COMP_OP: C19.1 R42.2 TP9.1 ; off-sheet COMP_OP
TEST: U6.3(B1) ; off-sheet TEST
TEST_EN: U6.6(S) ; off-sheet TEST_EN
VIN_ZC: U11.7(OUT) ; off-sheet VIN_ZC
NetC22_2: C22.2 C23.2 R13.2 R16.2 U5.3(IN+)
NetC27_1: C27.1 R14.1 R17.1 R18.2 R19.2 U7.4(VIN-)
NetC27_2: C27.2 C33.2 C36.2 R12.1 R14.2 R15.1 R17.2 TP6.1 U7.1(VOUT)
NetC28_1: C28.1 C29.1 R41.1 U5.1(OUT) U5.4(IN-)
NetC28_2: C28.2 C29.2 R12.2 R13.1 R15.2 R16.1
NetC30_1: C30.1 R24.1 R25.1 R26.1 R27.1 U8.4(VIN-)
NetC30_2: C30.2 J5.2 R26.2 R27.2 R31.2 R35.2 TP8.1 U8.1(VOUT)
NetC33_1: C33.1 C34.2 C35.2 C36.1 R31.1 R35.1
NetC34_1: C34.1 C35.1 R28.2 R29.2 U8.3(VIN+)
NetC43_1: C43.1 R45.1 R46.1 R48.2
NetJ5_1: J5.1 R34.1 R36.2 U9.3(IN+)
NetJ6_2: J6.2 R43.2
NetR10_2: R10.2 R44.1 U11.2(IN-)
NetR18_1: R18.1 R19.1 U6.4(A)
NetR20_1: R20.1 R21.1 TP7.1
NetR20_2: R20.2 R21.2 R22.1 R23.1 U7.3(VIN+)
NetR30_1: R30.1 R32.1(CCW) R32.2(WIPER) U9.4(IN-)
NetR34_2: R34.2 R42.1 U9.1(OUT)
NetR37_1: R37.1 R38.2 U10.1(REF)
NetR44_2: R44.2 R47.1 U11.1(OUT)
NetR46_2: R46.2 R49.2 U11.3(IN+)
NetTP5_1: TP5.1 U6.1(B2)

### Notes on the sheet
- Place these two jumpers next to each other
- Connect J5-2 and J6-2: bypass the comparator
- Connect J5-2 and J5-1: Comparator output is connecte to MSP

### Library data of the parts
C18 C19 C42 = GQM2195C2A100JB01D: CAP, CERM, 10 pF, 100 V, +/- 5%, C0G/NP0, 0805; Manufacturer: MuRata; Polarized: N; CompType: Capacitor; Value: 10pF; U/M: EA; Cap_F: 0.00000000001; Tolerance_%: 5; Value1: Unknown; VDC_V: 100; Value2: 100V; TaMin_C: -55; TaMax_C: 125; Cap_Case: 0805; SizeArea_mm2: 2.5; SizeAreaWB_mm2: 6.75; SizeX_mm: 2; SizeY_mm: 1.25; SizeZ_mm: 1.45; AEC Category: Q200
C22 C23 = CC0805JRNP09BN101: as C3 on sheet Sheet1
C24 C31 C37 C38 C44 = C1608X7R1C105K080AC: CAP, CERM, 1 µF, 16 V, +/- 10%, X7R, 0603; Manufacturer: TDK; Polarized: N; CompType: Capacitor; Value: 1uF; U/M: EA; Cap_F: 0.000001; Tolerance_%: 10; ESR_ohm: 0.0057; Value1: 0.0057 ohm; VDC_V: 16; Value2: 16V; TaMin_C: -55; TaMax_C: 125; SizeArea_mm2: 1.28; SizeAreaWB_mm2: 4.68; SizeX_mm: 1.6; SizeY_mm: 0.8; SizeZ_mm: 1; AEC Category: Q200
C25 C26 C32 C39 C40 C45 = 06033C104JAT2A: as C21 on sheet Sheet1
C27 C30 = GQM2195C1H220JB01D: as C16 on sheet Sheet1
C28 C29 = GRM2165C1H221JA01D: CAP, CERM, 220 pF, 50 V, +/- 5%, C0G/NP0, 0805; Manufacturer: MuRata; Polarized: N; CompType: Capacitor; Value: 220pF; U/M: EA; Cap_F: 0.00000000022; Tolerance_%: 5; Value1: Unknown; VDC_V: 50; Value2: 50V; TaMin_C: -55; TaMax_C: 125; Cap_Case: 0805; SizeArea_mm2: 2.5; SizeAreaWB_mm2: 6.75; SizeX_mm: 2; SizeY_mm: 1.25; SizeZ_mm: 1.45; AEC Category: Q200
C33-C36 C43 = GRM216R71E102KA01D: CAP, CERM, 1000 pF, 25 V, +/- 10%, X7R, 0805; Manufacturer: MuRata; Polarized: N; CompType: Capacitor; Value: 1000pF; U/M: EA; Cap_F: 0.000000001; Tolerance_%: 10; Value1: Unknown; VDC_V: 25; Value2: 25V; TaMin_C: -55; TaMax_C: 125; Cap_Case: 0805; SizeArea_mm2: 2.5; SizeAreaWB_mm2: 6.75; SizeX_mm: 2; SizeY_mm: 1.25; SizeZ_mm: 1.45; AEC Category: Q200
J5 J6 = PEC02SAAN: as J3 on sheet Sheet1
R10 R44 R46 R49 = CRCW060347K0JNEA: as R7 on sheet Sheet1
R12 R13 R15 R16 = CRCW080551K0JNEA: RES, 51 k, 5%, 0.125 W, 0805; Manufacturer: Vishay-Dale; CompType: Resistor; Value: 51k; Res_ohm: 51000; Value_Code: 51k0; Tolerance_%: 5; Power_W: 0.125; Value2: 0.125W; VDC_V: 150; TempCo: 200 ppm/C; SizeArea_mm2: 2.5; SizeX_mm: 2; SizeY_mm: 1.25; SizeZ_mm: 1.45; EIA_Code: E24; U/M: EA; AEC Category: Q200
R14 R17 R22 R23 R30 = CRCW0805100KFKEA: RES, 100 k, 1%, 0.125 W, 0805; Manufacturer: Vishay-Dale; CompType: Resistor; Value: 100k; Res_ohm: 100000; Tolerance_%: 1; Power_W: 0.125; Value2: 0.125W; VDC_V: 150; TempCo: 100 ppm/C; SizeArea_mm2: 2.5; SizeX_mm: 2; SizeY_mm: 1.25; SizeZ_mm: 1.45; EIA_Code: E96; U/M: EA; AEC Category: Q200
R18-R21 = CRCW080510K0FKEA: RES, 10.0 k, 1%, 0.125 W, 0805; Manufacturer: Vishay-Dale; CompType: Resistor; Value: 10.0k; Res_ohm: 10000; Value_Code: 10k0; Tolerance_%: 1; Power_W: 0.125; Value2: 0.125W; VDC_V: 150; TempCo: 100 ppm/C; SizeArea_mm2: 2.5; SizeX_mm: 2; SizeY_mm: 1.25; SizeZ_mm: 1.45; EIA_Code: E96; U/M: EA; AEC Category: Q200
R24 R25 R28 R29 = CRCW080520K0FKEA: RES, 20.0 k, 1%, 0.125 W, 0805; Manufacturer: Vishay-Dale; CompType: Resistor; Value: 20.0k; Res_ohm: 20000; Value_Code: 20k0; Tolerance_%: 1; Power_W: 0.125; Value2: 0.125W; VDC_V: 150; TempCo: 100 ppm/C; SizeArea_mm2: 2.5; SizeX_mm: 2; SizeY_mm: 1.25; SizeZ_mm: 1.45; EIA_Code: E96; U/M: EA; AEC Category: Q200
R26 R27 = CRCW0805180KJNEA: RES, 180 k, 5%, 0.125 W, 0805; Manufacturer: Vishay-Dale; CompType: Resistor; Value: 180k; Res_ohm: 180000; Tolerance_%: 5; Power_W: 0.125; Value2: 0.125W; VDC_V: 150; TempCo: 200 ppm/C; SizeArea_mm2: 2.5; SizeX_mm: 2; SizeY_mm: 1.25; SizeZ_mm: 1.45; EIA_Code: E24; U/M: EA; AEC Category: Q200
R31 R35 = CRCW0805120KJNEA: RES, 120 k, 5%, 0.125 W, 0805; Manufacturer: Vishay-Dale; CompType: Resistor; Value: 120k; Res_ohm: 120000; Tolerance_%: 5; Power_W: 0.125; Value2: 0.125W; VDC_V: 150; TempCo: 200 ppm/C; SizeArea_mm2: 2.5; SizeX_mm: 2; SizeY_mm: 1.25; SizeZ_mm: 1.45; EIA_Code: E24; U/M: EA; AEC Category: Q200
R32 = EVM-3YSX50B25: TRIMMER, 200k ohm, 0.15W, SMD; Manufacturer: Panasonic; Sim Note: Enter the Resistance value and the set point into parameter fields.; SymbolCreator: a0412235
R33 = CRCW06033K40FKEA: RES, 3.40 k, 1%, 0.1 W, 0603; Manufacturer: Vishay-Dale; CompType: Resistor; Value: 3.40k; Res_ohm: 3400; Value_Code: 3k40; Tolerance_%: 1; Power_W: 0.1; Value2: 0.1W; VDC_V: 75; TempCo: 100 ppm/C; SizeArea_mm2: 1.28; SizeX_mm: 1.6; SizeY_mm: 0.8; EIA_Code: E96; U/M: EA; AEC Category: Q200
R34 = CRCW08053M83FKEA: RES, 3.83 M, 1%, 0.125 W, 0805; Manufacturer: Vishay-Dale; CompType: Resistor; Value: 3.83Meg; Res_ohm: 3830000; Value_Code: 3M83; Tolerance_%: 1; Power_W: 0.125; Value2: 0.125W; VDC_V: 150; TempCo: 100 ppm/C; SizeArea_mm2: 2.5; SizeX_mm: 2; SizeY_mm: 1.25; SizeZ_mm: 1.45; EIA_Code: E96; U/M: EA; AEC Category: Q200
R36 = CRCW0805200KJNEA: RES, 200 k, 5%, 0.125 W, 0805; Manufacturer: Vishay-Dale; CompType: Resistor; Value: 200k; Res_ohm: 200000; Tolerance_%: 5; Power_W: 0.125; Value2: 0.125W; VDC_V: 150; TempCo: 200 ppm/C; SizeArea_mm2: 2.5; SizeX_mm: 2; SizeY_mm: 1.25; SizeZ_mm: 1.45; EIA_Code: E24; U/M: EA; AEC Category: Q200
R37 = CRCW060329K4FKEA: RES, 29.4 k, 1%, 0.1 W, 0603; Manufacturer: Vishay-Dale; CompType: Resistor; Value: 29.4k; Res_ohm: 29400; Value_Code: 29k4; Tolerance_%: 1; Power_W: 0.1; Value2: 0.1W; VDC_V: 75; TempCo: 100 ppm/C; SizeArea_mm2: 1.28; SizeX_mm: 1.6; SizeY_mm: 0.8; EIA_Code: E96; U/M: EA; AEC Category: Q200
R38 = CRCW0603100KFKEA: as R6 on sheet Sheet1
R41 = CRCW0805402RFKEA: RES, 402, 1%, 0.125 W, 0805; Manufacturer: Vishay-Dale; CompType: Resistor; Value: 402; Value_Code: 402R; Tolerance_%: 1; Power_W: 0.125; Value2: 0.125W; VDC_V: 150; TempCo: 100 ppm/C; SizeArea_mm2: 2.5; SizeX_mm: 2; SizeY_mm: 1.25; SizeZ_mm: 1.45; EIA_Code: E96; U/M: EA; AEC Category: Q200
R42 = CRCW08050000Z0EA: RES, 0, 5%, 0.125 W, 0805; Manufacturer: Vishay-Dale; CompType: Resistor; Value: 0; Value_Code: 0000; Tolerance_%: 5; Power_W: 0.125; Value2: 0.125W; VDC_V: 150; TempCo: 200 ppm/C; SizeArea_mm2: 2.5; SizeX_mm: 2; SizeY_mm: 1.25; SizeZ_mm: 1.45; EIA_Code: E24; U/M: EA; AEC Category: Q200
R43 = CRCW08051K00JNEA: RES, 1.0 k, 5%, 0.125 W, 0805; Manufacturer: Vishay-Dale; CompType: Resistor; Value: 1.0k; Res_ohm: 1000; Value_Code: 1k00; Tolerance_%: 5; Power_W: 0.125; Value2: 0.125W; VDC_V: 150; TempCo: 200 ppm/C; SizeArea_mm2: 2.5; SizeX_mm: 2; SizeY_mm: 1.25; SizeZ_mm: 1.45; EIA_Code: E24; U/M: EA; AEC Category: Q200
R45 = CRCW2010300KFKEF: RES, 300 k, 1%, 0.75 W, AEC-Q200 Grade 0, 2010; Manufacturer: Vishay-Dale; CompType: Resistor; Value: 300k; Res_ohm: 300000; Tolerance_%: 1; Power_W: 0.75; Value2: 0.75W; VDC_V: 400; TempCo: 100 ppm/C; SizeArea_mm2: 12.5; SizeX_mm: 5; SizeY_mm: 2.5; SizeZ_mm: 1.66; U/M: EA; AEC Category: Q200; AEC Qualified: Y; AEC Grade: 0
R47 = CRCW060310R0FKEA: RES, 10.0, 1%, 0.1 W, 0603; Manufacturer: Vishay-Dale; CompType: Resistor; Value: 10.0; Res_ohm: 10; Value_Code: 10R0; Tolerance_%: 1; Power_W: 0.1; Value2: 0.1W; VDC_V: 75; TempCo: 100 ppm/C; SizeArea_mm2: 1.28; SizeX_mm: 1.6; SizeY_mm: 0.8; EIA_Code: E96; U/M: EA; AEC Category: Q200
R48 = CRCW08051K10FKEA: RES, 1.10 k, 1%, 0.125 W, 0805; Manufacturer: Vishay-Dale; CompType: Resistor; Value: 1.10k; Res_ohm: 1100; Value_Code: 1k10; Tolerance_%: 1; Power_W: 0.125; Value2: 0.125W; VDC_V: 150; TempCo: 100 ppm/C; SizeArea_mm2: 2.5; SizeX_mm: 2; SizeY_mm: 1.25; SizeZ_mm: 1.45; EIA_Code: E96; U/M: EA; AEC Category: Q200
TP4-TP9 = 0253-0-15-15-30-27-10-0: Pin Receptacle, Dia 0.015-0.025", Length 0.173", Gold, TH; Manufacturer: Mill-Max; Gender: Female
U5 = TLV316IDBVR: 10-MHz, Rail-to-Rail Input/Output, Low-Voltage, 1.8-V CMOS Operational Amplifier, DBV0005A; Alternate PartNumber: TLV316IDBVT; Manufacturer: Texas Instruments; SizeArea_mm2: 8.12; SizeAreaWB_mm2: 14.82; SizeX_mm: 2.8; SizeY_mm: 2.9; SizeZ_mm: 1.45; CompType: IC; U/M: EA
U6 = SN74LVC1G3157DRYR: SINGLE-POLE DOUBLE-THROW ANALOG SWITCH, DRY0006A; Manufacturer: Texas Instruments; SymbolCreator: a0799628; SizeArea_mm2: 1.45; SizeAreaWB_mm2: 4.9; SizeX_mm: 1; SizeZ_mm: 0.6; CompType: IC; U/M: EA
U7 = OPA835IDBVR: Ultra Low Power, Rail-to-Rail Out, Negative Rail In, VFB Amplifier, 2.5 to 5.5 V, -40 to 125 degC, 6-pin SOT23 (DBV6), Green (RoHS & no Sb/Br); Alternate Manufacturer: Texas Instruments; Alternate PartNumber: Equivalent; 2nd Harmonic(dBc): 70; 3rd Harmonic(dBc): 73; @ MHz: 1; BW @ Acl(MHz): 56; Iib(Max)(nA): 400; Io(Typ)(mA): 40; Iq per channel(Max)(mA): 0.25; Settling Time (0.1%)(Typ)(ns): 55; Slew Rate(Typ)(V/us): 160; Sub Family: Audio Operational Amplifier, High Speed Amplifier (>=50MHz), Low Noise Amp (<=10nV/rtHz), Low Offset Voltage Amplifier (<=500uV), Low Power Amp (<=500uA), Low Supply Voltage Amplifier (<=2.7V); Vio(Max)(mV): 0.5; Vn at Flatband(Typ)(nV/rtHz): 9.3; Vs(Max)(V): 5.5; Vs(Min)(V): 2.5
U8 = OPA836IDBVR: Very Low Power, Rail to Rail Out, Negative Rail In, VFB Operational Amplifier, 2.5 to 5.5 V, -40 to 125 degC, 6-pin SOT23 (DBV6), Green (RoHS & no Sb/Br); Alternate Manufacturer: Texas Instruments; Alternate PartNumber: Equivalent; 2nd Harmonic(dBc): 85; 3rd Harmonic(dBc): 105; @ MHz: 1; BW @ Acl(MHz): 205; Iib(Max)(nA): 1000; Io(Typ)(mA): 50; Settling Time (0.1%)(Typ)(ns): 30; Slew Rate(Typ)(V/us): 560; Sub Family: Audio Operational Amplifier, High Output Current Amplifier (>=50mA), High Speed Amplifier (>=50MHz), Low Noise Amp (<=10nV/rtHz), Low Offset Voltage Amplifier (<=500uV), Low Supply Voltage Amplifier (<=2.7V); Vio(Max)(mV): 0.4; Vn at Flatband(Typ)(nV/rtHz): 4.6; Vs(Max)(V): 5.5; Vs(Min)(V): 2.5
U9 = TLV3201AIDBVR: 40-ns, microPOWER, Push-Pull Output Comparators, DBV0005A; Alternate PartNumber: TLV3201AIDBVT; Manufacturer: Texas Instruments; SizeArea_mm2: 8.12; SizeAreaWB_mm2: 14.82; SizeX_mm: 2.8; SizeY_mm: 2.9; SizeZ_mm: 1.45; CompType: IC; U/M: EA
U10 = TLV431AIDBZR: Low Voltage Adjustable Precision Shunt Regulator, 39 ppm / degC, 15 mA, -40 to 85 degC, 3-pin SOT-23 (DBZ), Green (RoHS & no Sb/Br); Manufacturer: Texas Instruments; Alternate PartNumber: Equivalent; Initial Accuracy @ 25/deg C(%): 1; Iout/Iz(Max)(mA): 15; Min Iz for Regulation(uA): 80; Rating: Catalog; SubFamily: Shunt Voltage Reference; Temp Coeff(Max)(ppm/ degree C): 129; Temp Coeff(Typ)(ppm/ degree C): 39; VO Adj(Max)(V): 6; VO Adj(Min)(V): 1.24
U11 = LMV612MA: Dual 1.4 MHz, Low Power General Purpose, 1.8V Op Amp, D0008A; Manufacturer: Texas Instruments; CompType: OpAmp IC

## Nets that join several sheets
+1.6V: Sheet1 (R39.1), Sheet2 (7 pins)
+3.3V: Sheet1 (14 pins), Sheet2 (21 pins)
AGND: Sheet1 (38 pins), Sheet2 (34 pins)
Vac_in: Sheet1 (D4.2 J7.3 RF1.2), Sheet2 (R45.2)
ADC_HF: Sheet1 (U3.3), Sheet2 (C42.1 R43.1)
ADC_LF: Sheet1 (U3.1), Sheet2 (C18.1 R41.2 TP4.1)
ADC_VIN: Sheet1 (TP12.1 U3.11), Sheet2 (R47.2 U11.5)
COMP_OP: Sheet1 (U3.24), Sheet2 (C19.1 R42.2 TP9.1)
TEST: Sheet1 (R9.2), Sheet2 (U6.3)
TEST_EN: Sheet1 (U3.2), Sheet2 (U6.6)
VIN_ZC: Sheet1 (TP11.1 U3.10), Sheet2 (U11.7)

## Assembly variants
3.2kHz: not fitted C12 C13 C19 C20 C23 C27 C29 C30 C33 C34 R8 R9 R14 R15 R16 R18 R21 R23 R24 R26 R28 R31 R39 R40
50kHz: not fitted C12 C13 C19 C20 C22 C27 C28 C30 C33 C34 R8 R9 R12 R13 R14 R18 R21 R23 R24 R26 R28 R31 R39 R40; alternate parts C23 -> GRM2165C2A911JA01D, C29 -> GRM216R71E182KA01D, R15 -> CRCW080510K0FKEA, R16 -> CRCW080510K0FKEA
100kHz: not fitted C12 C13 C19 C20 C22 C27 C28 C30 C33 C34 R8 R9 R12 R13 R14 R18 R21 R23 R24 R26 R28 R31 R39 R40; alternate parts C23 -> CC0805JRNP09BN101, C29 -> GRM2165C1H221JA01D, R15 -> CRCW080510K0FKEA, R16 -> CRCW080510K0FKEA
